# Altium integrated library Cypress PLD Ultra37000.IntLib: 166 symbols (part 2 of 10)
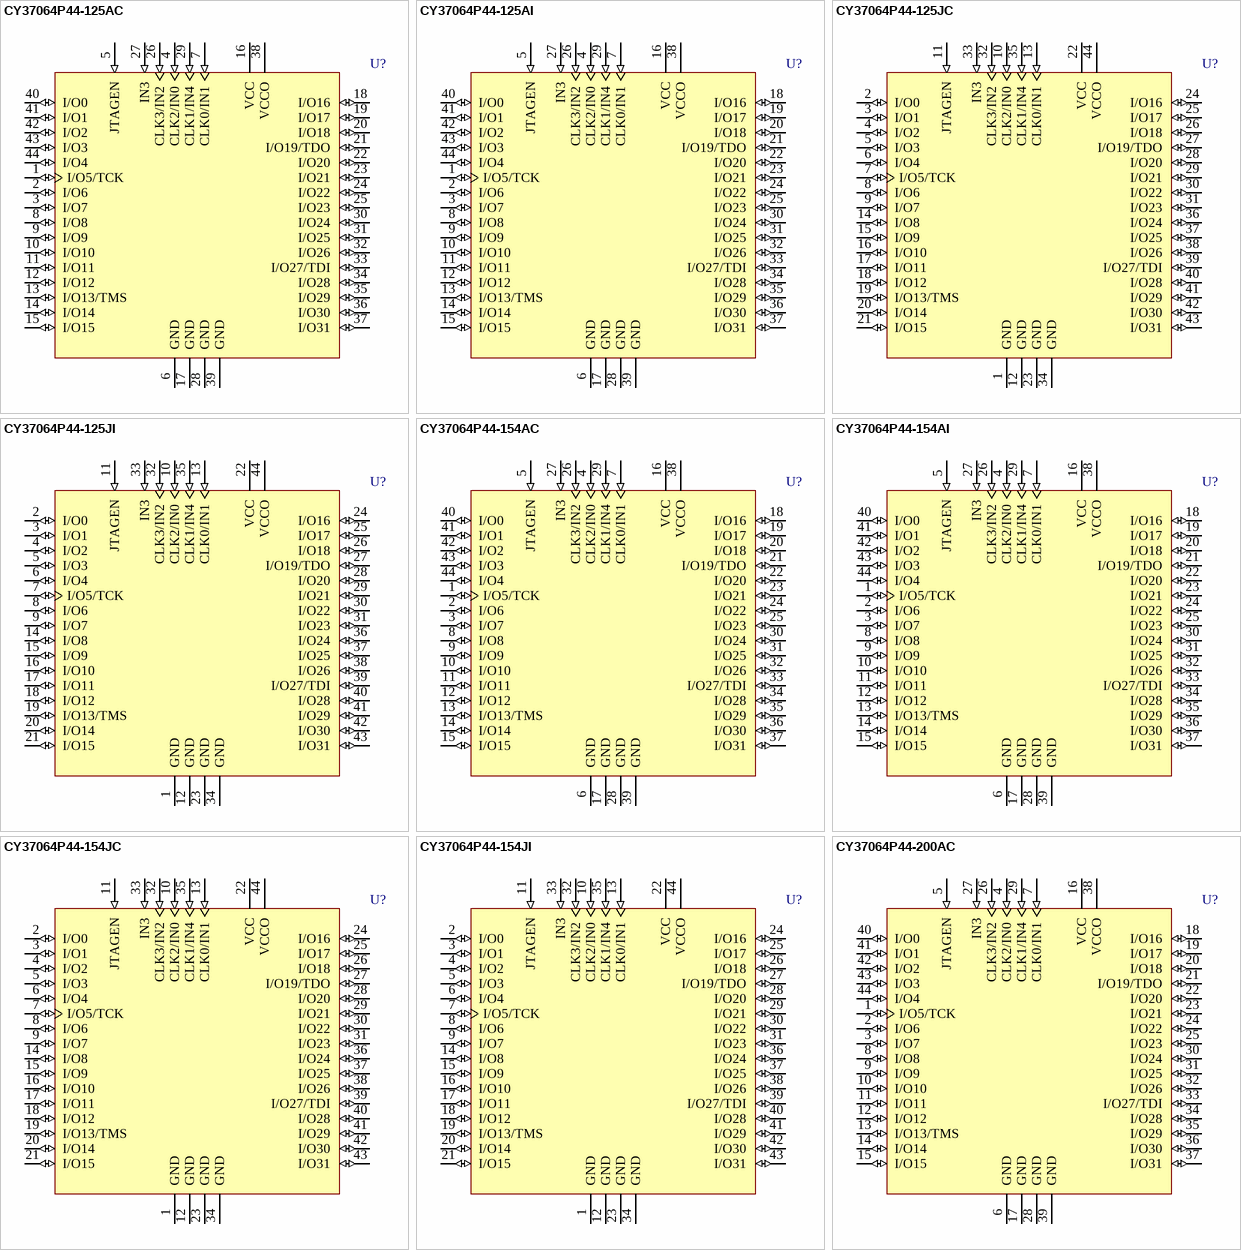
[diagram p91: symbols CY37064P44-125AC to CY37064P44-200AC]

## CY37064P44-125JC
designator U?
Ultra37000 5V, ISR High-Performance CPLD
footprint J67_N (Leaded Chip Carrier, 44-Leads, Body 16.6x16.6mm, Pitch 1.27mm, IPC Medium Density)
footprint J67_L (Leaded Chip Carrier, 44-Leads, Body 16.6x16.6mm, Pitch 1.27mm, IPC High Density)
footprint J67_M (Leaded Chip Carrier, 44-Leads, Body 16.6x16.6mm, Pitch 1.27mm, IPC Low Density)
3D model CY37064P44-J67 (44-Pin Plastic Leaded Chip Carrier 1.27 mm Pitch)
pins: 1 GND (power), 2 I/O0 (io), 3 I/O1 (io), 4 I/O2 (io), 5 I/O3 (io), 6 I/O4 (io), 7 I/O5/TCK (io), 8 I/O6 (io), 9 I/O7 (io), 10 CLK2/IN0 (in), 11 JTAGEN (in), 12 GND (power), 13 CLK0/IN1 (in), 14 I/O8 (io), 15 I/O9 (io), 16 I/O10 (io), 17 I/O11 (io), 18 I/O12 (io), 19 I/O13/TMS (io), 20 I/O14 (io), 21 I/O15 (io), 22 VCC (power), 23 GND (power), 24 I/O16 (io), 25 I/O17 (io), 26 I/O18 (io), 27 I/O19/TDO (io), 28 I/O20 (io), 29 I/O21 (io), 30 I/O22 (io), 31 I/O23 (io), 32 CLK3/IN2 (in), 33 IN3 (in), 34 GND (power), 35 CLK1/IN4 (in), 36 I/O24 (io), 37 I/O25 (io), 38 I/O26 (io), 39 I/O27/TDI (io), 40 I/O28 (io), 41 I/O29 (io), 42 I/O30 (io), 43 I/O31 (io), 44 VCCO (power)

## CY37064P44-125JI
designator U?
Ultra37000 5V, ISR High-Performance CPLD
footprint J67_N (Leaded Chip Carrier, 44-Leads, Body 16.6x16.6mm, Pitch 1.27mm, IPC Medium Density)
footprint J67_L (Leaded Chip Carrier, 44-Leads, Body 16.6x16.6mm, Pitch 1.27mm, IPC High Density)
footprint J67_M (Leaded Chip Carrier, 44-Leads, Body 16.6x16.6mm, Pitch 1.27mm, IPC Low Density)
3D model CY37064P44-J67 (44-Pin Plastic Leaded Chip Carrier 1.27 mm Pitch)
pins: 1 GND (power), 2 I/O0 (io), 3 I/O1 (io), 4 I/O2 (io), 5 I/O3 (io), 6 I/O4 (io), 7 I/O5/TCK (io), 8 I/O6 (io), 9 I/O7 (io), 10 CLK2/IN0 (in), 11 JTAGEN (in), 12 GND (power), 13 CLK0/IN1 (in), 14 I/O8 (io), 15 I/O9 (io), 16 I/O10 (io), 17 I/O11 (io), 18 I/O12 (io), 19 I/O13/TMS (io), 20 I/O14 (io), 21 I/O15 (io), 22 VCC (power), 23 GND (power), 24 I/O16 (io), 25 I/O17 (io), 26 I/O18 (io), 27 I/O19/TDO (io), 28 I/O20 (io), 29 I/O21 (io), 30 I/O22 (io), 31 I/O23 (io), 32 CLK3/IN2 (in), 33 IN3 (in), 34 GND (power), 35 CLK1/IN4 (in), 36 I/O24 (io), 37 I/O25 (io), 38 I/O26 (io), 39 I/O27/TDI (io), 40 I/O28 (io), 41 I/O29 (io), 42 I/O30 (io), 43 I/O31 (io), 44 VCCO (power)

## CY37064P44-154AC
designator U?
Ultra37000 5V, ISR High-Performance CPLD
footprint A44_N (Thin QFP, 44-Leads, Body 10x10mm, Pitch 0.8mm, IPC Medium Density)
footprint A44_L (Thin QFP, 44-Leads, Body 10x10mm, Pitch 0.8mm, IPC High Density)
footprint A44_M (Thin QFP, 44-Leads, Body 10x10mm, Pitch 0.8mm, IPC Low Density)
3D model CY37064P44-A44 (44-Pin Thin Plastic Quad Flat Pack 0.8 mm Pitch)
pins: 1 I/O5/TCK (io), 2 I/O6 (io), 3 I/O7 (io), 4 CLK2/IN0 (in), 5 JTAGEN (in), 6 GND (power), 7 CLK0/IN1 (in), 8 I/O8 (io), 9 I/O9 (io), 10 I/O10 (io), 11 I/O11 (io), 12 I/O12 (io), 13 I/O13/TMS (io), 14 I/O14 (io), 15 I/O15 (io), 16 VCC (power), 17 GND (power), 18 I/O16 (io), 19 I/O17 (io), 20 I/O18 (io), 21 I/O19/TDO (io), 22 I/O20 (io), 23 I/O21 (io), 24 I/O22 (io), 25 I/O23 (io), 26 CLK3/IN2 (in), 27 IN3 (in), 28 GND (power), 29 CLK1/IN4 (in), 30 I/O24 (io), 31 I/O25 (io), 32 I/O26 (io), 33 I/O27/TDI (io), 34 I/O28 (io), 35 I/O29 (io), 36 I/O30 (io), 37 I/O31 (io), 38 VCCO (power), 39 GND (power), 40 I/O0 (io), 41 I/O1 (io), 42 I/O2 (io), 43 I/O3 (io), 44 I/O4 (io)

## CY37064P44-154AI
designator U?
Ultra37000 5V, ISR High-Performance CPLD
footprint A44_N (Thin QFP, 44-Leads, Body 10x10mm, Pitch 0.8mm, IPC Medium Density)
footprint A44_L (Thin QFP, 44-Leads, Body 10x10mm, Pitch 0.8mm, IPC High Density)
footprint A44_M (Thin QFP, 44-Leads, Body 10x10mm, Pitch 0.8mm, IPC Low Density)
3D model CY37064P44-A44 (44-Pin Thin Plastic Quad Flat Pack 0.8 mm Pitch)
pins: 1 I/O5/TCK (io), 2 I/O6 (io), 3 I/O7 (io), 4 CLK2/IN0 (in), 5 JTAGEN (in), 6 GND (power), 7 CLK0/IN1 (in), 8 I/O8 (io), 9 I/O9 (io), 10 I/O10 (io), 11 I/O11 (io), 12 I/O12 (io), 13 I/O13/TMS (io), 14 I/O14 (io), 15 I/O15 (io), 16 VCC (power), 17 GND (power), 18 I/O16 (io), 19 I/O17 (io), 20 I/O18 (io), 21 I/O19/TDO (io), 22 I/O20 (io), 23 I/O21 (io), 24 I/O22 (io), 25 I/O23 (io), 26 CLK3/IN2 (in), 27 IN3 (in), 28 GND (power), 29 CLK1/IN4 (in), 30 I/O24 (io), 31 I/O25 (io), 32 I/O26 (io), 33 I/O27/TDI (io), 34 I/O28 (io), 35 I/O29 (io), 36 I/O30 (io), 37 I/O31 (io), 38 VCCO (power), 39 GND (power), 40 I/O0 (io), 41 I/O1 (io), 42 I/O2 (io), 43 I/O3 (io), 44 I/O4 (io)

## CY37064P44-154JC
designator U?
Ultra37000 5V, ISR High-Performance CPLD
footprint J67_N (Leaded Chip Carrier, 44-Leads, Body 16.6x16.6mm, Pitch 1.27mm, IPC Medium Density)
footprint J67_L (Leaded Chip Carrier, 44-Leads, Body 16.6x16.6mm, Pitch 1.27mm, IPC High Density)
footprint J67_M (Leaded Chip Carrier, 44-Leads, Body 16.6x16.6mm, Pitch 1.27mm, IPC Low Density)
3D model CY37064P44-J67 (44-Pin Plastic Leaded Chip Carrier 1.27 mm Pitch)
pins: 1 GND (power), 2 I/O0 (io), 3 I/O1 (io), 4 I/O2 (io), 5 I/O3 (io), 6 I/O4 (io), 7 I/O5/TCK (io), 8 I/O6 (io), 9 I/O7 (io), 10 CLK2/IN0 (in), 11 JTAGEN (in), 12 GND (power), 13 CLK0/IN1 (in), 14 I/O8 (io), 15 I/O9 (io), 16 I/O10 (io), 17 I/O11 (io), 18 I/O12 (io), 19 I/O13/TMS (io), 20 I/O14 (io), 21 I/O15 (io), 22 VCC (power), 23 GND (power), 24 I/O16 (io), 25 I/O17 (io), 26 I/O18 (io), 27 I/O19/TDO (io), 28 I/O20 (io), 29 I/O21 (io), 30 I/O22 (io), 31 I/O23 (io), 32 CLK3/IN2 (in), 33 IN3 (in), 34 GND (power), 35 CLK1/IN4 (in), 36 I/O24 (io), 37 I/O25 (io), 38 I/O26 (io), 39 I/O27/TDI (io), 40 I/O28 (io), 41 I/O29 (io), 42 I/O30 (io), 43 I/O31 (io), 44 VCCO (power)

## CY37064P44-154JI
designator U?
Ultra37000 5V, ISR High-Performance CPLD
footprint J67_N (Leaded Chip Carrier, 44-Leads, Body 16.6x16.6mm, Pitch 1.27mm, IPC Medium Density)
footprint J67_L (Leaded Chip Carrier, 44-Leads, Body 16.6x16.6mm, Pitch 1.27mm, IPC High Density)
footprint J67_M (Leaded Chip Carrier, 44-Leads, Body 16.6x16.6mm, Pitch 1.27mm, IPC Low Density)
3D model CY37064P44-J67 (44-Pin Plastic Leaded Chip Carrier 1.27 mm Pitch)
pins: 1 GND (power), 2 I/O0 (io), 3 I/O1 (io), 4 I/O2 (io), 5 I/O3 (io), 6 I/O4 (io), 7 I/O5/TCK (io), 8 I/O6 (io), 9 I/O7 (io), 10 CLK2/IN0 (in), 11 JTAGEN (in), 12 GND (power), 13 CLK0/IN1 (in), 14 I/O8 (io), 15 I/O9 (io), 16 I/O10 (io), 17 I/O11 (io), 18 I/O12 (io), 19 I/O13/TMS (io), 20 I/O14 (io), 21 I/O15 (io), 22 VCC (power), 23 GND (power), 24 I/O16 (io), 25 I/O17 (io), 26 I/O18 (io), 27 I/O19/TDO (io), 28 I/O20 (io), 29 I/O21 (io), 30 I/O22 (io), 31 I/O23 (io), 32 CLK3/IN2 (in), 33 IN3 (in), 34 GND (power), 35 CLK1/IN4 (in), 36 I/O24 (io), 37 I/O25 (io), 38 I/O26 (io), 39 I/O27/TDI (io), 40 I/O28 (io), 41 I/O29 (io), 42 I/O30 (io), 43 I/O31 (io), 44 VCCO (power)

## CY37064P44-200AC
designator U?
Ultra37000 5V, ISR High-Performance CPLD
footprint A44_N (Thin QFP, 44-Leads, Body 10x10mm, Pitch 0.8mm, IPC Medium Density)
footprint A44_L (Thin QFP, 44-Leads, Body 10x10mm, Pitch 0.8mm, IPC High Density)
footprint A44_M (Thin QFP, 44-Leads, Body 10x10mm, Pitch 0.8mm, IPC Low Density)
3D model CY37064P44-A44 (44-Pin Thin Plastic Quad Flat Pack 0.8 mm Pitch)
pins: 1 I/O5/TCK (io), 2 I/O6 (io), 3 I/O7 (io), 4 CLK2/IN0 (in), 5 JTAGEN (in), 6 GND (power), 7 CLK0/IN1 (in), 8 I/O8 (io), 9 I/O9 (io), 10 I/O10 (io), 11 I/O11 (io), 12 I/O12 (io), 13 I/O13/TMS (io), 14 I/O14 (io), 15 I/O15 (io), 16 VCC (power), 17 GND (power), 18 I/O16 (io), 19 I/O17 (io), 20 I/O18 (io), 21 I/O19/TDO (io), 22 I/O20 (io), 23 I/O21 (io), 24 I/O22 (io), 25 I/O23 (io), 26 CLK3/IN2 (in), 27 IN3 (in), 28 GND (power), 29 CLK1/IN4 (in), 30 I/O24 (io), 31 I/O25 (io), 32 I/O26 (io), 33 I/O27/TDI (io), 34 I/O28 (io), 35 I/O29 (io), 36 I/O30 (io), 37 I/O31 (io), 38 VCCO (power), 39 GND (power), 40 I/O0 (io), 41 I/O1 (io), 42 I/O2 (io), 43 I/O3 (io), 44 I/O4 (io)

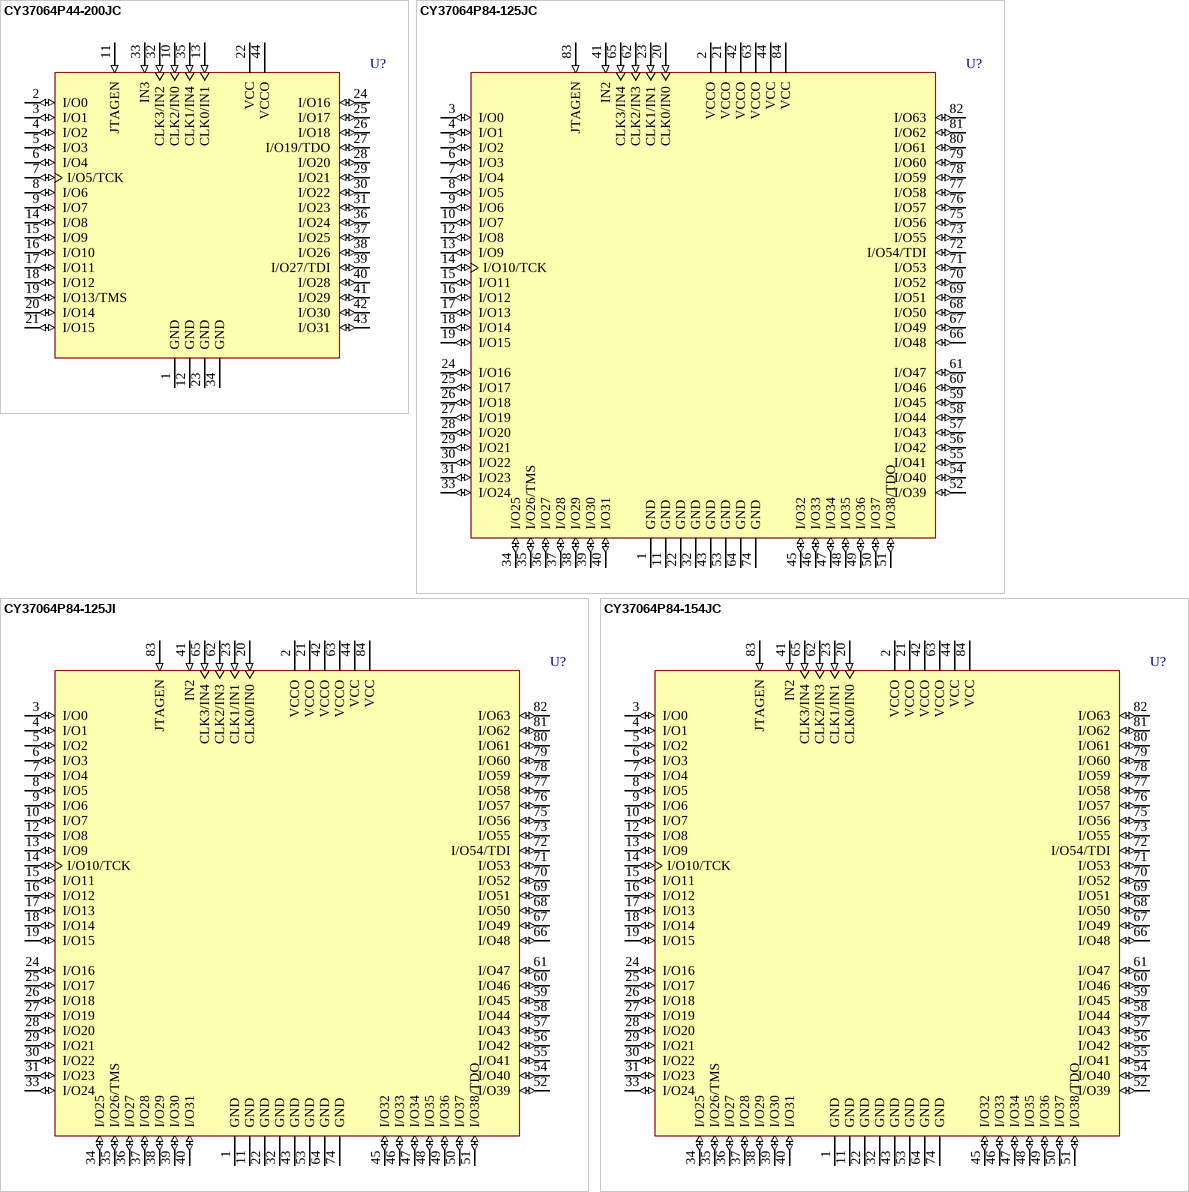
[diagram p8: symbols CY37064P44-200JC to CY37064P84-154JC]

## CY37064P44-200JC
designator U?
Ultra37000 5V, ISR High-Performance CPLD
footprint J67_N (Leaded Chip Carrier, 44-Leads, Body 16.6x16.6mm, Pitch 1.27mm, IPC Medium Density)
footprint J67_L (Leaded Chip Carrier, 44-Leads, Body 16.6x16.6mm, Pitch 1.27mm, IPC High Density)
footprint J67_M (Leaded Chip Carrier, 44-Leads, Body 16.6x16.6mm, Pitch 1.27mm, IPC Low Density)
3D model CY37064P44-J67 (44-Pin Plastic Leaded Chip Carrier 1.27 mm Pitch)
pins: 1 GND (power), 2 I/O0 (io), 3 I/O1 (io), 4 I/O2 (io), 5 I/O3 (io), 6 I/O4 (io), 7 I/O5/TCK (io), 8 I/O6 (io), 9 I/O7 (io), 10 CLK2/IN0 (in), 11 JTAGEN (in), 12 GND (power), 13 CLK0/IN1 (in), 14 I/O8 (io), 15 I/O9 (io), 16 I/O10 (io), 17 I/O11 (io), 18 I/O12 (io), 19 I/O13/TMS (io), 20 I/O14 (io), 21 I/O15 (io), 22 VCC (power), 23 GND (power), 24 I/O16 (io), 25 I/O17 (io), 26 I/O18 (io), 27 I/O19/TDO (io), 28 I/O20 (io), 29 I/O21 (io), 30 I/O22 (io), 31 I/O23 (io), 32 CLK3/IN2 (in), 33 IN3 (in), 34 GND (power), 35 CLK1/IN4 (in), 36 I/O24 (io), 37 I/O25 (io), 38 I/O26 (io), 39 I/O27/TDI (io), 40 I/O28 (io), 41 I/O29 (io), 42 I/O30 (io), 43 I/O31 (io), 44 VCCO (power)

## CY37064P84-125JC
designator U?
Ultra37000 5V, ISR High-Performance CPLD
footprint J83_N (Leaded Chip Carrier, 84-Leads, Body 29.3x29.3mm, Pitch 1.27mm, IPC Medium Density)
footprint J83_L (Leaded Chip Carrier, 84-Leads, Body 29.3x29.3mm, Pitch 1.27mm, IPC High Density)
footprint J83_M (Leaded Chip Carrier, 84-Leads, Body 29.3x29.3mm, Pitch 1.27mm, IPC Low Density)
3D model CY37064P84-J83 (84-Pin Plastic Leaded Chip Carrier 1.27 mm Pitch)
pins: 1 GND (power), 2 VCCO (power), 3 I/O0 (io), 4 I/O1 (io), 5 I/O2 (io), 6 I/O3 (io), 7 I/O4 (io), 8 I/O5 (io), 9 I/O6 (io), 10 I/O7 (io), 11 GND (power), 12 I/O8 (io), 13 I/O9 (io), 14 I/O10/TCK (io), 15 I/O11 (io), 16 I/O12 (io), 17 I/O13 (io), 18 I/O14 (io), 19 I/O15 (io), 20 CLK0/IN0 (in), 21 VCCO (power), 22 GND (power), 23 CLK1/IN1 (in), 24 I/O16 (io), 25 I/O17 (io), 26 I/O18 (io), 27 I/O19 (io), 28 I/O20 (io), 29 I/O21 (io), 30 I/O22 (io), 31 I/O23 (io), 32 GND (power), 33 I/O24 (io), 34 I/O25 (io), 35 I/O26/TMS (io), 36 I/O27 (io), 37 I/O28 (io), 38 I/O29 (io), 39 I/O30 (io), 40 I/O31 (io), 41 IN2 (in), 42 VCCO (power), 43 GND (power), 44 VCC (power), 45 I/O32 (io), 46 I/O33 (io), 47 I/O34 (io), 48 I/O35 (io), 49 I/O36 (io), 50 I/O37 (io), 51 I/O38/TDO (io), 52 I/O39 (io), 53 GND (power), 54 I/O40 (io), 55 I/O41 (io), 56 I/O42 (io), 57 I/O43 (io), 58 I/O44 (io), 59 I/O45 (io), 60 I/O46 (io), 61 I/O47 (io), 62 CLK2/IN3 (in), 63 VCCO (power), 64 GND (power), 65 CLK3/IN4 (in), 66 I/O48 (io), 67 I/O49 (io), 68 I/O50 (io), 69 I/O51 (io), 70 I/O52 (io), 71 I/O53 (io), 72 I/O54/TDI (io), 73 I/O55 (io), 74 GND (power), 75 I/O56 (io), 76 I/O57 (io), 77 I/O58 (io), 78 I/O59 (io), 79 I/O60 (io), 80 I/O61 (io), 81 I/O62 (io), 82 I/O63 (io), 83 JTAGEN (in), 84 VCC (power)

## CY37064P84-125JI
designator U?
Ultra37000 5V, ISR High-Performance CPLD
footprint J83_N (Leaded Chip Carrier, 84-Leads, Body 29.3x29.3mm, Pitch 1.27mm, IPC Medium Density)
footprint J83_L (Leaded Chip Carrier, 84-Leads, Body 29.3x29.3mm, Pitch 1.27mm, IPC High Density)
footprint J83_M (Leaded Chip Carrier, 84-Leads, Body 29.3x29.3mm, Pitch 1.27mm, IPC Low Density)
3D model CY37064P84-J83 (84-Pin Plastic Leaded Chip Carrier 1.27 mm Pitch)
pins: 1 GND (power), 2 VCCO (power), 3 I/O0 (io), 4 I/O1 (io), 5 I/O2 (io), 6 I/O3 (io), 7 I/O4 (io), 8 I/O5 (io), 9 I/O6 (io), 10 I/O7 (io), 11 GND (power), 12 I/O8 (io), 13 I/O9 (io), 14 I/O10/TCK (io), 15 I/O11 (io), 16 I/O12 (io), 17 I/O13 (io), 18 I/O14 (io), 19 I/O15 (io), 20 CLK0/IN0 (in), 21 VCCO (power), 22 GND (power), 23 CLK1/IN1 (in), 24 I/O16 (io), 25 I/O17 (io), 26 I/O18 (io), 27 I/O19 (io), 28 I/O20 (io), 29 I/O21 (io), 30 I/O22 (io), 31 I/O23 (io), 32 GND (power), 33 I/O24 (io), 34 I/O25 (io), 35 I/O26/TMS (io), 36 I/O27 (io), 37 I/O28 (io), 38 I/O29 (io), 39 I/O30 (io), 40 I/O31 (io), 41 IN2 (in), 42 VCCO (power), 43 GND (power), 44 VCC (power), 45 I/O32 (io), 46 I/O33 (io), 47 I/O34 (io), 48 I/O35 (io), 49 I/O36 (io), 50 I/O37 (io), 51 I/O38/TDO (io), 52 I/O39 (io), 53 GND (power), 54 I/O40 (io), 55 I/O41 (io), 56 I/O42 (io), 57 I/O43 (io), 58 I/O44 (io), 59 I/O45 (io), 60 I/O46 (io), 61 I/O47 (io), 62 CLK2/IN3 (in), 63 VCCO (power), 64 GND (power), 65 CLK3/IN4 (in), 66 I/O48 (io), 67 I/O49 (io), 68 I/O50 (io), 69 I/O51 (io), 70 I/O52 (io), 71 I/O53 (io), 72 I/O54/TDI (io), 73 I/O55 (io), 74 GND (power), 75 I/O56 (io), 76 I/O57 (io), 77 I/O58 (io), 78 I/O59 (io), 79 I/O60 (io), 80 I/O61 (io), 81 I/O62 (io), 82 I/O63 (io), 83 JTAGEN (in), 84 VCC (power)

## CY37064P84-154JC
designator U?
Ultra37000 5V, ISR High-Performance CPLD
footprint J83_N (Leaded Chip Carrier, 84-Leads, Body 29.3x29.3mm, Pitch 1.27mm, IPC Medium Density)
footprint J83_L (Leaded Chip Carrier, 84-Leads, Body 29.3x29.3mm, Pitch 1.27mm, IPC High Density)
footprint J83_M (Leaded Chip Carrier, 84-Leads, Body 29.3x29.3mm, Pitch 1.27mm, IPC Low Density)
3D model CY37064P84-J83 (84-Pin Plastic Leaded Chip Carrier 1.27 mm Pitch)
pins: 1 GND (power), 2 VCCO (power), 3 I/O0 (io), 4 I/O1 (io), 5 I/O2 (io), 6 I/O3 (io), 7 I/O4 (io), 8 I/O5 (io), 9 I/O6 (io), 10 I/O7 (io), 11 GND (power), 12 I/O8 (io), 13 I/O9 (io), 14 I/O10/TCK (io), 15 I/O11 (io), 16 I/O12 (io), 17 I/O13 (io), 18 I/O14 (io), 19 I/O15 (io), 20 CLK0/IN0 (in), 21 VCCO (power), 22 GND (power), 23 CLK1/IN1 (in), 24 I/O16 (io), 25 I/O17 (io), 26 I/O18 (io), 27 I/O19 (io), 28 I/O20 (io), 29 I/O21 (io), 30 I/O22 (io), 31 I/O23 (io), 32 GND (power), 33 I/O24 (io), 34 I/O25 (io), 35 I/O26/TMS (io), 36 I/O27 (io), 37 I/O28 (io), 38 I/O29 (io), 39 I/O30 (io), 40 I/O31 (io), 41 IN2 (in), 42 VCCO (power), 43 GND (power), 44 VCC (power), 45 I/O32 (io), 46 I/O33 (io), 47 I/O34 (io), 48 I/O35 (io), 49 I/O36 (io), 50 I/O37 (io), 51 I/O38/TDO (io), 52 I/O39 (io), 53 GND (power), 54 I/O40 (io), 55 I/O41 (io), 56 I/O42 (io), 57 I/O43 (io), 58 I/O44 (io), 59 I/O45 (io), 60 I/O46 (io), 61 I/O47 (io), 62 CLK2/IN3 (in), 63 VCCO (power), 64 GND (power), 65 CLK3/IN4 (in), 66 I/O48 (io), 67 I/O49 (io), 68 I/O50 (io), 69 I/O51 (io), 70 I/O52 (io), 71 I/O53 (io), 72 I/O54/TDI (io), 73 I/O55 (io), 74 GND (power), 75 I/O56 (io), 76 I/O57 (io), 77 I/O58 (io), 78 I/O59 (io), 79 I/O60 (io), 80 I/O61 (io), 81 I/O62 (io), 82 I/O63 (io), 83 JTAGEN (in), 84 VCC (power)

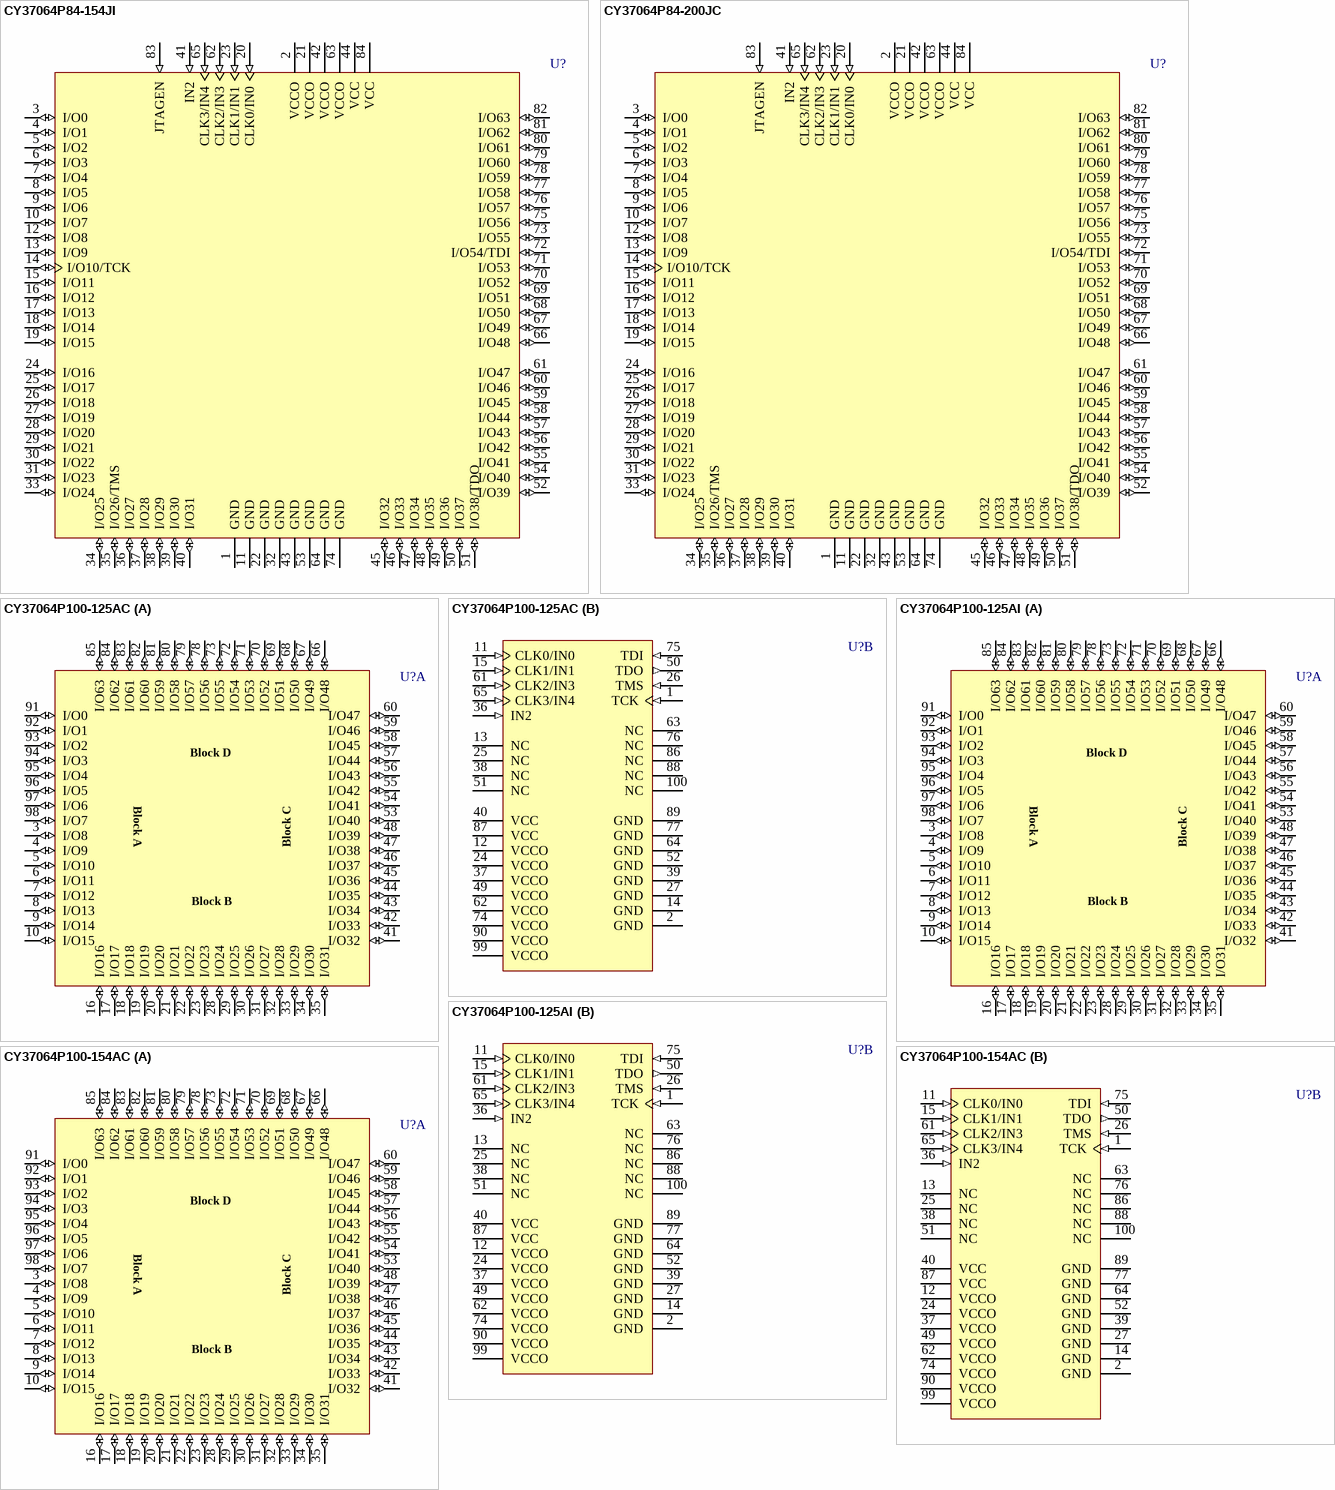
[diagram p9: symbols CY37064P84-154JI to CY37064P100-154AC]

## CY37064P84-154JI
designator U?
Ultra37000 5V, ISR High-Performance CPLD
footprint J83_N (Leaded Chip Carrier, 84-Leads, Body 29.3x29.3mm, Pitch 1.27mm, IPC Medium Density)
footprint J83_L (Leaded Chip Carrier, 84-Leads, Body 29.3x29.3mm, Pitch 1.27mm, IPC High Density)
footprint J83_M (Leaded Chip Carrier, 84-Leads, Body 29.3x29.3mm, Pitch 1.27mm, IPC Low Density)
3D model CY37064P84-J83 (84-Pin Plastic Leaded Chip Carrier 1.27 mm Pitch)
pins: 1 GND (power), 2 VCCO (power), 3 I/O0 (io), 4 I/O1 (io), 5 I/O2 (io), 6 I/O3 (io), 7 I/O4 (io), 8 I/O5 (io), 9 I/O6 (io), 10 I/O7 (io), 11 GND (power), 12 I/O8 (io), 13 I/O9 (io), 14 I/O10/TCK (io), 15 I/O11 (io), 16 I/O12 (io), 17 I/O13 (io), 18 I/O14 (io), 19 I/O15 (io), 20 CLK0/IN0 (in), 21 VCCO (power), 22 GND (power), 23 CLK1/IN1 (in), 24 I/O16 (io), 25 I/O17 (io), 26 I/O18 (io), 27 I/O19 (io), 28 I/O20 (io), 29 I/O21 (io), 30 I/O22 (io), 31 I/O23 (io), 32 GND (power), 33 I/O24 (io), 34 I/O25 (io), 35 I/O26/TMS (io), 36 I/O27 (io), 37 I/O28 (io), 38 I/O29 (io), 39 I/O30 (io), 40 I/O31 (io), 41 IN2 (in), 42 VCCO (power), 43 GND (power), 44 VCC (power), 45 I/O32 (io), 46 I/O33 (io), 47 I/O34 (io), 48 I/O35 (io), 49 I/O36 (io), 50 I/O37 (io), 51 I/O38/TDO (io), 52 I/O39 (io), 53 GND (power), 54 I/O40 (io), 55 I/O41 (io), 56 I/O42 (io), 57 I/O43 (io), 58 I/O44 (io), 59 I/O45 (io), 60 I/O46 (io), 61 I/O47 (io), 62 CLK2/IN3 (in), 63 VCCO (power), 64 GND (power), 65 CLK3/IN4 (in), 66 I/O48 (io), 67 I/O49 (io), 68 I/O50 (io), 69 I/O51 (io), 70 I/O52 (io), 71 I/O53 (io), 72 I/O54/TDI (io), 73 I/O55 (io), 74 GND (power), 75 I/O56 (io), 76 I/O57 (io), 77 I/O58 (io), 78 I/O59 (io), 79 I/O60 (io), 80 I/O61 (io), 81 I/O62 (io), 82 I/O63 (io), 83 JTAGEN (in), 84 VCC (power)

## CY37064P84-200JC
designator U?
Ultra37000 5V, ISR High-Performance CPLD
footprint J83_N (Leaded Chip Carrier, 84-Leads, Body 29.3x29.3mm, Pitch 1.27mm, IPC Medium Density)
footprint J83_L (Leaded Chip Carrier, 84-Leads, Body 29.3x29.3mm, Pitch 1.27mm, IPC High Density)
footprint J83_M (Leaded Chip Carrier, 84-Leads, Body 29.3x29.3mm, Pitch 1.27mm, IPC Low Density)
3D model CY37064P84-J83 (84-Pin Plastic Leaded Chip Carrier 1.27 mm Pitch)
pins: 1 GND (power), 2 VCCO (power), 3 I/O0 (io), 4 I/O1 (io), 5 I/O2 (io), 6 I/O3 (io), 7 I/O4 (io), 8 I/O5 (io), 9 I/O6 (io), 10 I/O7 (io), 11 GND (power), 12 I/O8 (io), 13 I/O9 (io), 14 I/O10/TCK (io), 15 I/O11 (io), 16 I/O12 (io), 17 I/O13 (io), 18 I/O14 (io), 19 I/O15 (io), 20 CLK0/IN0 (in), 21 VCCO (power), 22 GND (power), 23 CLK1/IN1 (in), 24 I/O16 (io), 25 I/O17 (io), 26 I/O18 (io), 27 I/O19 (io), 28 I/O20 (io), 29 I/O21 (io), 30 I/O22 (io), 31 I/O23 (io), 32 GND (power), 33 I/O24 (io), 34 I/O25 (io), 35 I/O26/TMS (io), 36 I/O27 (io), 37 I/O28 (io), 38 I/O29 (io), 39 I/O30 (io), 40 I/O31 (io), 41 IN2 (in), 42 VCCO (power), 43 GND (power), 44 VCC (power), 45 I/O32 (io), 46 I/O33 (io), 47 I/O34 (io), 48 I/O35 (io), 49 I/O36 (io), 50 I/O37 (io), 51 I/O38/TDO (io), 52 I/O39 (io), 53 GND (power), 54 I/O40 (io), 55 I/O41 (io), 56 I/O42 (io), 57 I/O43 (io), 58 I/O44 (io), 59 I/O45 (io), 60 I/O46 (io), 61 I/O47 (io), 62 CLK2/IN3 (in), 63 VCCO (power), 64 GND (power), 65 CLK3/IN4 (in), 66 I/O48 (io), 67 I/O49 (io), 68 I/O50 (io), 69 I/O51 (io), 70 I/O52 (io), 71 I/O53 (io), 72 I/O54/TDI (io), 73 I/O55 (io), 74 GND (power), 75 I/O56 (io), 76 I/O57 (io), 77 I/O58 (io), 78 I/O59 (io), 79 I/O60 (io), 80 I/O61 (io), 81 I/O62 (io), 82 I/O63 (io), 83 JTAGEN (in), 84 VCC (power)

## CY37064P100-125AC
designator U?
Ultra37000 5V, ISR High-Performance CPLD
footprint A100_N (Thin QFP, 100-Leads, Body 14x14mm, Pitch 0.5mm, IPC Medium Density)
footprint A100_L (Thin QFP, 100-Leads, Body 14x14mm, Pitch 0.5mm, IPC High Density)
footprint A100_M (Thin QFP, 100-Leads, Body 14x14mm, Pitch 0.5mm, IPC Low Density)
3D model CY37064P100-A100 (100-Pin Thin Quad Flat Pack 0.5 mm Pitch)
part A pins: 3 I/O8 (io), 4 I/O9 (io), 5 I/O10 (io), 6 I/O11 (io), 7 I/O12 (io), 8 I/O13 (io), 9 I/O14 (io), 10 I/O15 (io), 16 I/O16 (io), 17 I/O17 (io), 18 I/O18 (io), 19 I/O19 (io), 20 I/O20 (io), 21 I/O21 (io), 22 I/O22 (io), 23 I/O23 (io), 28 I/O24 (io), 29 I/O25 (io), 30 I/O26 (io), 31 I/O27 (io), 32 I/O28 (io), 33 I/O29 (io), 34 I/O30 (io), 35 I/O31 (io), 41 I/O32 (io), 42 I/O33 (io), 43 I/O34 (io), 44 I/O35 (io), 45 I/O36 (io), 46 I/O37 (io), 47 I/O38 (io), 48 I/O39 (io), 53 I/O40 (io), 54 I/O41 (io), 55 I/O42 (io), 56 I/O43 (io), 57 I/O44 (io), 58 I/O45 (io), 59 I/O46 (io), 60 I/O47 (io), 66 I/O48 (io), 67 I/O49 (io), 68 I/O50 (io), 69 I/O51 (io), 70 I/O52 (io), 71 I/O53 (io), 72 I/O54 (io), 73 I/O55 (io), 78 I/O56 (io), 79 I/O57 (io), 80 I/O58 (io), 81 I/O59 (io), 82 I/O60 (io), 83 I/O61 (io), 84 I/O62 (io), 85 I/O63 (io), 91 I/O0 (io), 92 I/O1 (io), 93 I/O2 (io), 94 I/O3 (io), 95 I/O4 (io), 96 I/O5 (io), 97 I/O6 (io), 98 I/O7 (io)
part B pins: 1 TCK (in), 2 GND (power), 11 CLK0/IN0 (in), 12 VCCO (power), 13 NC, 14 GND (power), 15 CLK1/IN1 (in), 24 VCCO (power), 25 NC, 26 TMS (in), 27 GND (power), 36 IN2 (in), 37 VCCO (power), 38 NC, 39 GND (power), 40 VCC (power), 49 VCCO (power), 50 TDO (out), 51 NC, 52 GND (power), 61 CLK2/IN3 (in), 62 VCCO (power), 63 NC, 64 GND (power), 65 CLK3/IN4 (in), 74 VCCO (power), 75 TDI (in), 76 NC, 77 GND (power), 86 NC, 87 VCC (power), 88 NC, 89 GND (power), 90 VCCO (power), 99 VCCO (power), 100 NC

## CY37064P100-125AI
designator U?
Ultra37000 5V, ISR High-Performance CPLD
footprint A100_N (Thin QFP, 100-Leads, Body 14x14mm, Pitch 0.5mm, IPC Medium Density)
footprint A100_L (Thin QFP, 100-Leads, Body 14x14mm, Pitch 0.5mm, IPC High Density)
footprint A100_M (Thin QFP, 100-Leads, Body 14x14mm, Pitch 0.5mm, IPC Low Density)
3D model CY37064P100-A100 (100-Pin Thin Quad Flat Pack 0.5 mm Pitch)
part A pins: 3 I/O8 (io), 4 I/O9 (io), 5 I/O10 (io), 6 I/O11 (io), 7 I/O12 (io), 8 I/O13 (io), 9 I/O14 (io), 10 I/O15 (io), 16 I/O16 (io), 17 I/O17 (io), 18 I/O18 (io), 19 I/O19 (io), 20 I/O20 (io), 21 I/O21 (io), 22 I/O22 (io), 23 I/O23 (io), 28 I/O24 (io), 29 I/O25 (io), 30 I/O26 (io), 31 I/O27 (io), 32 I/O28 (io), 33 I/O29 (io), 34 I/O30 (io), 35 I/O31 (io), 41 I/O32 (io), 42 I/O33 (io), 43 I/O34 (io), 44 I/O35 (io), 45 I/O36 (io), 46 I/O37 (io), 47 I/O38 (io), 48 I/O39 (io), 53 I/O40 (io), 54 I/O41 (io), 55 I/O42 (io), 56 I/O43 (io), 57 I/O44 (io), 58 I/O45 (io), 59 I/O46 (io), 60 I/O47 (io), 66 I/O48 (io), 67 I/O49 (io), 68 I/O50 (io), 69 I/O51 (io), 70 I/O52 (io), 71 I/O53 (io), 72 I/O54 (io), 73 I/O55 (io), 78 I/O56 (io), 79 I/O57 (io), 80 I/O58 (io), 81 I/O59 (io), 82 I/O60 (io), 83 I/O61 (io), 84 I/O62 (io), 85 I/O63 (io), 91 I/O0 (io), 92 I/O1 (io), 93 I/O2 (io), 94 I/O3 (io), 95 I/O4 (io), 96 I/O5 (io), 97 I/O6 (io), 98 I/O7 (io)
part B pins: 1 TCK (in), 2 GND (power), 11 CLK0/IN0 (in), 12 VCCO (power), 13 NC, 14 GND (power), 15 CLK1/IN1 (in), 24 VCCO (power), 25 NC, 26 TMS (in), 27 GND (power), 36 IN2 (in), 37 VCCO (power), 38 NC, 39 GND (power), 40 VCC (power), 49 VCCO (power), 50 TDO (out), 51 NC, 52 GND (power), 61 CLK2/IN3 (in), 62 VCCO (power), 63 NC, 64 GND (power), 65 CLK3/IN4 (in), 74 VCCO (power), 75 TDI (in), 76 NC, 77 GND (power), 86 NC, 87 VCC (power), 88 NC, 89 GND (power), 90 VCCO (power), 99 VCCO (power), 100 NC

## CY37064P100-154AC
designator U?
Ultra37000 5V, ISR High-Performance CPLD
footprint A100_N (Thin QFP, 100-Leads, Body 14x14mm, Pitch 0.5mm, IPC Medium Density)
footprint A100_L (Thin QFP, 100-Leads, Body 14x14mm, Pitch 0.5mm, IPC High Density)
footprint A100_M (Thin QFP, 100-Leads, Body 14x14mm, Pitch 0.5mm, IPC Low Density)
3D model CY37064P100-A100 (100-Pin Thin Quad Flat Pack 0.5 mm Pitch)
part A pins: 3 I/O8 (io), 4 I/O9 (io), 5 I/O10 (io), 6 I/O11 (io), 7 I/O12 (io), 8 I/O13 (io), 9 I/O14 (io), 10 I/O15 (io), 16 I/O16 (io), 17 I/O17 (io), 18 I/O18 (io), 19 I/O19 (io), 20 I/O20 (io), 21 I/O21 (io), 22 I/O22 (io), 23 I/O23 (io), 28 I/O24 (io), 29 I/O25 (io), 30 I/O26 (io), 31 I/O27 (io), 32 I/O28 (io), 33 I/O29 (io), 34 I/O30 (io), 35 I/O31 (io), 41 I/O32 (io), 42 I/O33 (io), 43 I/O34 (io), 44 I/O35 (io), 45 I/O36 (io), 46 I/O37 (io), 47 I/O38 (io), 48 I/O39 (io), 53 I/O40 (io), 54 I/O41 (io), 55 I/O42 (io), 56 I/O43 (io), 57 I/O44 (io), 58 I/O45 (io), 59 I/O46 (io), 60 I/O47 (io), 66 I/O48 (io), 67 I/O49 (io), 68 I/O50 (io), 69 I/O51 (io), 70 I/O52 (io), 71 I/O53 (io), 72 I/O54 (io), 73 I/O55 (io), 78 I/O56 (io), 79 I/O57 (io), 80 I/O58 (io), 81 I/O59 (io), 82 I/O60 (io), 83 I/O61 (io), 84 I/O62 (io), 85 I/O63 (io), 91 I/O0 (io), 92 I/O1 (io), 93 I/O2 (io), 94 I/O3 (io), 95 I/O4 (io), 96 I/O5 (io), 97 I/O6 (io), 98 I/O7 (io)
part B pins: 1 TCK (in), 2 GND (power), 11 CLK0/IN0 (in), 12 VCCO (power), 13 NC, 14 GND (power), 15 CLK1/IN1 (in), 24 VCCO (power), 25 NC, 26 TMS (in), 27 GND (power), 36 IN2 (in), 37 VCCO (power), 38 NC, 39 GND (power), 40 VCC (power), 49 VCCO (power), 50 TDO (out), 51 NC, 52 GND (power), 61 CLK2/IN3 (in), 62 VCCO (power), 63 NC, 64 GND (power), 65 CLK3/IN4 (in), 74 VCCO (power), 75 TDI (in), 76 NC, 77 GND (power), 86 NC, 87 VCC (power), 88 NC, 89 GND (power), 90 VCCO (power), 99 VCCO (power), 100 NC

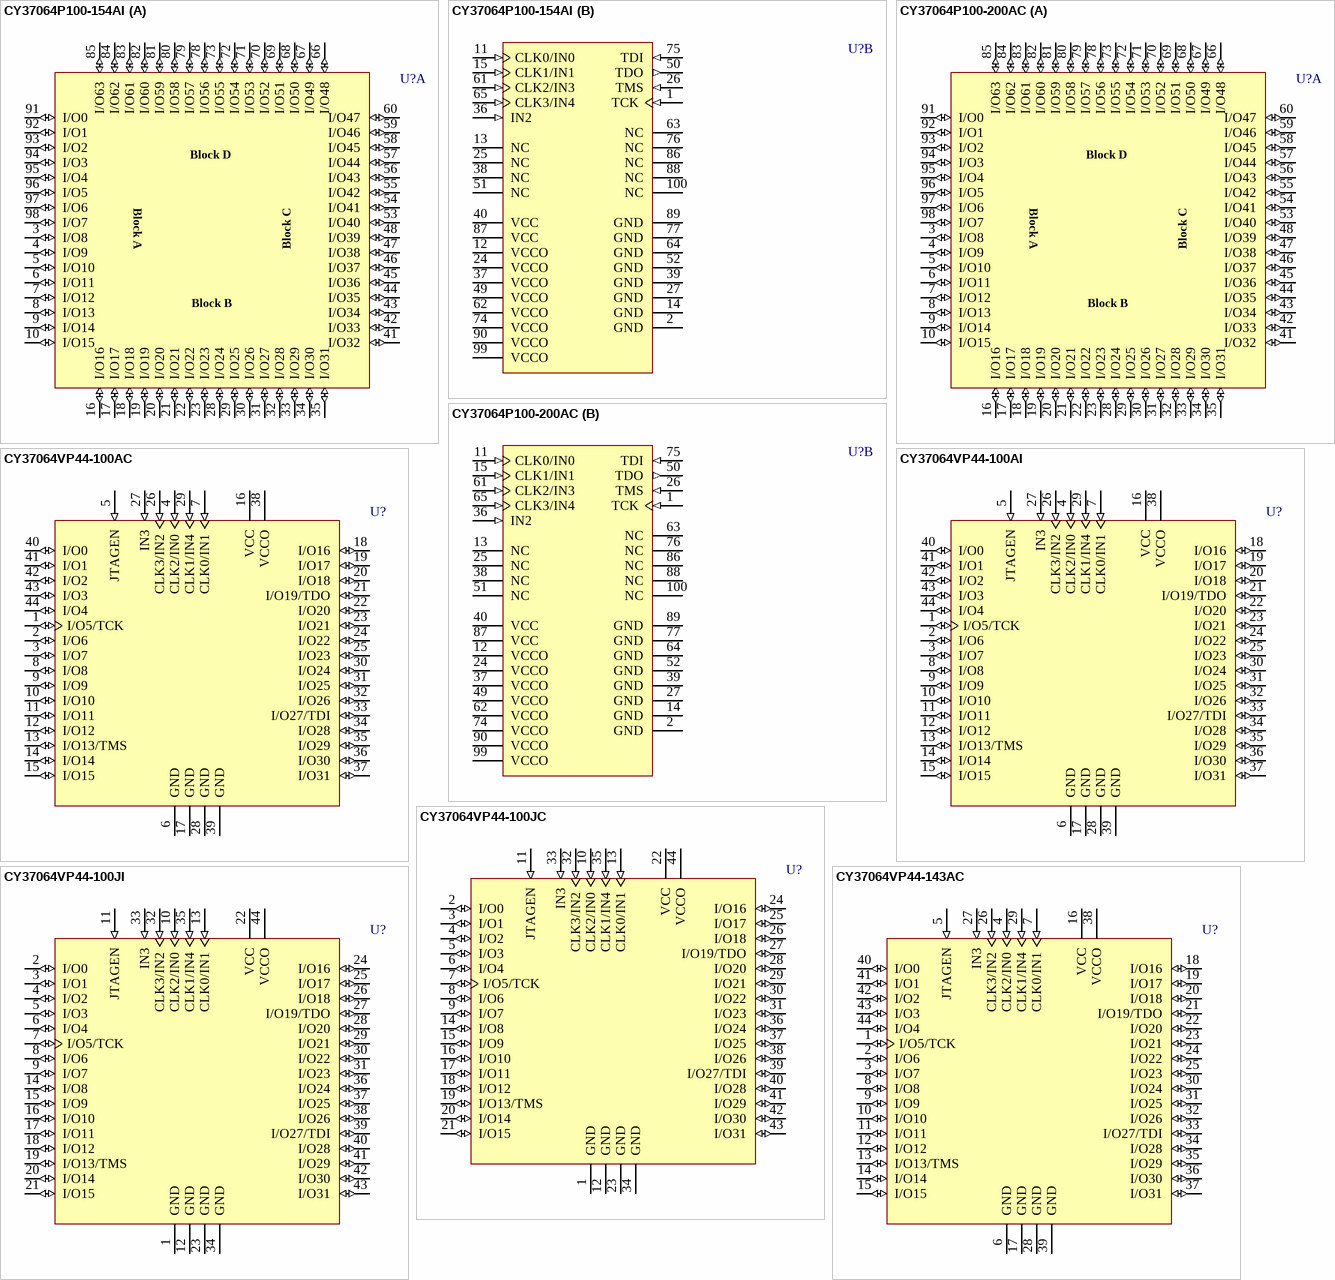
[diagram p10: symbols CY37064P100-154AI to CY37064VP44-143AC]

## CY37064P100-154AI
designator U?
Ultra37000 5V, ISR High-Performance CPLD
footprint A100_N (Thin QFP, 100-Leads, Body 14x14mm, Pitch 0.5mm, IPC Medium Density)
footprint A100_L (Thin QFP, 100-Leads, Body 14x14mm, Pitch 0.5mm, IPC High Density)
footprint A100_M (Thin QFP, 100-Leads, Body 14x14mm, Pitch 0.5mm, IPC Low Density)
3D model CY37064P100-A100 (100-Pin Thin Quad Flat Pack 0.5 mm Pitch)
part A pins: 3 I/O8 (io), 4 I/O9 (io), 5 I/O10 (io), 6 I/O11 (io), 7 I/O12 (io), 8 I/O13 (io), 9 I/O14 (io), 10 I/O15 (io), 16 I/O16 (io), 17 I/O17 (io), 18 I/O18 (io), 19 I/O19 (io), 20 I/O20 (io), 21 I/O21 (io), 22 I/O22 (io), 23 I/O23 (io), 28 I/O24 (io), 29 I/O25 (io), 30 I/O26 (io), 31 I/O27 (io), 32 I/O28 (io), 33 I/O29 (io), 34 I/O30 (io), 35 I/O31 (io), 41 I/O32 (io), 42 I/O33 (io), 43 I/O34 (io), 44 I/O35 (io), 45 I/O36 (io), 46 I/O37 (io), 47 I/O38 (io), 48 I/O39 (io), 53 I/O40 (io), 54 I/O41 (io), 55 I/O42 (io), 56 I/O43 (io), 57 I/O44 (io), 58 I/O45 (io), 59 I/O46 (io), 60 I/O47 (io), 66 I/O48 (io), 67 I/O49 (io), 68 I/O50 (io), 69 I/O51 (io), 70 I/O52 (io), 71 I/O53 (io), 72 I/O54 (io), 73 I/O55 (io), 78 I/O56 (io), 79 I/O57 (io), 80 I/O58 (io), 81 I/O59 (io), 82 I/O60 (io), 83 I/O61 (io), 84 I/O62 (io), 85 I/O63 (io), 91 I/O0 (io), 92 I/O1 (io), 93 I/O2 (io), 94 I/O3 (io), 95 I/O4 (io), 96 I/O5 (io), 97 I/O6 (io), 98 I/O7 (io)
part B pins: 1 TCK (in), 2 GND (power), 11 CLK0/IN0 (in), 12 VCCO (power), 13 NC, 14 GND (power), 15 CLK1/IN1 (in), 24 VCCO (power), 25 NC, 26 TMS (in), 27 GND (power), 36 IN2 (in), 37 VCCO (power), 38 NC, 39 GND (power), 40 VCC (power), 49 VCCO (power), 50 TDO (out), 51 NC, 52 GND (power), 61 CLK2/IN3 (in), 62 VCCO (power), 63 NC, 64 GND (power), 65 CLK3/IN4 (in), 74 VCCO (power), 75 TDI (in), 76 NC, 77 GND (power), 86 NC, 87 VCC (power), 88 NC, 89 GND (power), 90 VCCO (power), 99 VCCO (power), 100 NC

## CY37064P100-200AC
designator U?
Ultra37000 5V, ISR High-Performance CPLD
footprint A100_N (Thin QFP, 100-Leads, Body 14x14mm, Pitch 0.5mm, IPC Medium Density)
footprint A100_L (Thin QFP, 100-Leads, Body 14x14mm, Pitch 0.5mm, IPC High Density)
footprint A100_M (Thin QFP, 100-Leads, Body 14x14mm, Pitch 0.5mm, IPC Low Density)
3D model CY37064P100-A100 (100-Pin Thin Quad Flat Pack 0.5 mm Pitch)
part A pins: 3 I/O8 (io), 4 I/O9 (io), 5 I/O10 (io), 6 I/O11 (io), 7 I/O12 (io), 8 I/O13 (io), 9 I/O14 (io), 10 I/O15 (io), 16 I/O16 (io), 17 I/O17 (io), 18 I/O18 (io), 19 I/O19 (io), 20 I/O20 (io), 21 I/O21 (io), 22 I/O22 (io), 23 I/O23 (io), 28 I/O24 (io), 29 I/O25 (io), 30 I/O26 (io), 31 I/O27 (io), 32 I/O28 (io), 33 I/O29 (io), 34 I/O30 (io), 35 I/O31 (io), 41 I/O32 (io), 42 I/O33 (io), 43 I/O34 (io), 44 I/O35 (io), 45 I/O36 (io), 46 I/O37 (io), 47 I/O38 (io), 48 I/O39 (io), 53 I/O40 (io), 54 I/O41 (io), 55 I/O42 (io), 56 I/O43 (io), 57 I/O44 (io), 58 I/O45 (io), 59 I/O46 (io), 60 I/O47 (io), 66 I/O48 (io), 67 I/O49 (io), 68 I/O50 (io), 69 I/O51 (io), 70 I/O52 (io), 71 I/O53 (io), 72 I/O54 (io), 73 I/O55 (io), 78 I/O56 (io), 79 I/O57 (io), 80 I/O58 (io), 81 I/O59 (io), 82 I/O60 (io), 83 I/O61 (io), 84 I/O62 (io), 85 I/O63 (io), 91 I/O0 (io), 92 I/O1 (io), 93 I/O2 (io), 94 I/O3 (io), 95 I/O4 (io), 96 I/O5 (io), 97 I/O6 (io), 98 I/O7 (io)
part B pins: 1 TCK (in), 2 GND (power), 11 CLK0/IN0 (in), 12 VCCO (power), 13 NC, 14 GND (power), 15 CLK1/IN1 (in), 24 VCCO (power), 25 NC, 26 TMS (in), 27 GND (power), 36 IN2 (in), 37 VCCO (power), 38 NC, 39 GND (power), 40 VCC (power), 49 VCCO (power), 50 TDO (out), 51 NC, 52 GND (power), 61 CLK2/IN3 (in), 62 VCCO (power), 63 NC, 64 GND (power), 65 CLK3/IN4 (in), 74 VCCO (power), 75 TDI (in), 76 NC, 77 GND (power), 86 NC, 87 VCC (power), 88 NC, 89 GND (power), 90 VCCO (power), 99 VCCO (power), 100 NC

## CY37064VP44-100AC
designator U?
Ultra37000 3.3V, ISR High-Performance CPLD
footprint A44_N (Thin QFP, 44-Leads, Body 10x10mm, Pitch 0.8mm, IPC Medium Density)
footprint A44_L (Thin QFP, 44-Leads, Body 10x10mm, Pitch 0.8mm, IPC High Density)
footprint A44_M (Thin QFP, 44-Leads, Body 10x10mm, Pitch 0.8mm, IPC Low Density)
3D model CY37064VP44-A44 (44-Pin Thin Plastic Quad Flat Pack 0.8 mm Pitch)
pins: 1 I/O5/TCK (io), 2 I/O6 (io), 3 I/O7 (io), 4 CLK2/IN0 (in), 5 JTAGEN (in), 6 GND (power), 7 CLK0/IN1 (in), 8 I/O8 (io), 9 I/O9 (io), 10 I/O10 (io), 11 I/O11 (io), 12 I/O12 (io), 13 I/O13/TMS (io), 14 I/O14 (io), 15 I/O15 (io), 16 VCC (power), 17 GND (power), 18 I/O16 (io), 19 I/O17 (io), 20 I/O18 (io), 21 I/O19/TDO (io), 22 I/O20 (io), 23 I/O21 (io), 24 I/O22 (io), 25 I/O23 (io), 26 CLK3/IN2 (in), 27 IN3 (in), 28 GND (power), 29 CLK1/IN4 (in), 30 I/O24 (io), 31 I/O25 (io), 32 I/O26 (io), 33 I/O27/TDI (io), 34 I/O28 (io), 35 I/O29 (io), 36 I/O30 (io), 37 I/O31 (io), 38 VCCO (power), 39 GND (power), 40 I/O0 (io), 41 I/O1 (io), 42 I/O2 (io), 43 I/O3 (io), 44 I/O4 (io)

## CY37064VP44-100AI
designator U?
Ultra37000 3.3V, ISR High-Performance CPLD
footprint A44_N (Thin QFP, 44-Leads, Body 10x10mm, Pitch 0.8mm, IPC Medium Density)
footprint A44_L (Thin QFP, 44-Leads, Body 10x10mm, Pitch 0.8mm, IPC High Density)
footprint A44_M (Thin QFP, 44-Leads, Body 10x10mm, Pitch 0.8mm, IPC Low Density)
3D model CY37064VP44-A44 (44-Pin Thin Plastic Quad Flat Pack 0.8 mm Pitch)
pins: 1 I/O5/TCK (io), 2 I/O6 (io), 3 I/O7 (io), 4 CLK2/IN0 (in), 5 JTAGEN (in), 6 GND (power), 7 CLK0/IN1 (in), 8 I/O8 (io), 9 I/O9 (io), 10 I/O10 (io), 11 I/O11 (io), 12 I/O12 (io), 13 I/O13/TMS (io), 14 I/O14 (io), 15 I/O15 (io), 16 VCC (power), 17 GND (power), 18 I/O16 (io), 19 I/O17 (io), 20 I/O18 (io), 21 I/O19/TDO (io), 22 I/O20 (io), 23 I/O21 (io), 24 I/O22 (io), 25 I/O23 (io), 26 CLK3/IN2 (in), 27 IN3 (in), 28 GND (power), 29 CLK1/IN4 (in), 30 I/O24 (io), 31 I/O25 (io), 32 I/O26 (io), 33 I/O27/TDI (io), 34 I/O28 (io), 35 I/O29 (io), 36 I/O30 (io), 37 I/O31 (io), 38 VCCO (power), 39 GND (power), 40 I/O0 (io), 41 I/O1 (io), 42 I/O2 (io), 43 I/O3 (io), 44 I/O4 (io)

## CY37064VP44-100JC
designator U?
Ultra37000 3.3V, ISR High-Performance CPLD; ComponentAvailability: Obsolete
footprint J67_N (Leaded Chip Carrier, 44-Leads, Body 16.6x16.6mm, Pitch 1.27mm, IPC Medium Density)
footprint J67_L (Leaded Chip Carrier, 44-Leads, Body 16.6x16.6mm, Pitch 1.27mm, IPC High Density)
footprint J67_M (Leaded Chip Carrier, 44-Leads, Body 16.6x16.6mm, Pitch 1.27mm, IPC Low Density)
3D model CY37064VP44-J67 (44-Pin Plastic Leaded Chip Carrier 1.27 mm Pitch)
pins: 1 GND (power), 2 I/O0 (io), 3 I/O1 (io), 4 I/O2 (io), 5 I/O3 (io), 6 I/O4 (io), 7 I/O5/TCK (io), 8 I/O6 (io), 9 I/O7 (io), 10 CLK2/IN0 (in), 11 JTAGEN (in), 12 GND (power), 13 CLK0/IN1 (in), 14 I/O8 (io), 15 I/O9 (io), 16 I/O10 (io), 17 I/O11 (io), 18 I/O12 (io), 19 I/O13/TMS (io), 20 I/O14 (io), 21 I/O15 (io), 22 VCC (power), 23 GND (power), 24 I/O16 (io), 25 I/O17 (io), 26 I/O18 (io), 27 I/O19/TDO (io), 28 I/O20 (io), 29 I/O21 (io), 30 I/O22 (io), 31 I/O23 (io), 32 CLK3/IN2 (in), 33 IN3 (in), 34 GND (power), 35 CLK1/IN4 (in), 36 I/O24 (io), 37 I/O25 (io), 38 I/O26 (io), 39 I/O27/TDI (io), 40 I/O28 (io), 41 I/O29 (io), 42 I/O30 (io), 43 I/O31 (io), 44 VCCO (power)

## CY37064VP44-100JI
designator U?
Ultra37000 3.3V, ISR High-Performance CPLD; ComponentAvailability: Obsolete
footprint J67_N (Leaded Chip Carrier, 44-Leads, Body 16.6x16.6mm, Pitch 1.27mm, IPC Medium Density)
footprint J67_L (Leaded Chip Carrier, 44-Leads, Body 16.6x16.6mm, Pitch 1.27mm, IPC High Density)
footprint J67_M (Leaded Chip Carrier, 44-Leads, Body 16.6x16.6mm, Pitch 1.27mm, IPC Low Density)
3D model CY37064VP44-J67 (44-Pin Plastic Leaded Chip Carrier 1.27 mm Pitch)
pins: 1 GND (power), 2 I/O0 (io), 3 I/O1 (io), 4 I/O2 (io), 5 I/O3 (io), 6 I/O4 (io), 7 I/O5/TCK (io), 8 I/O6 (io), 9 I/O7 (io), 10 CLK2/IN0 (in), 11 JTAGEN (in), 12 GND (power), 13 CLK0/IN1 (in), 14 I/O8 (io), 15 I/O9 (io), 16 I/O10 (io), 17 I/O11 (io), 18 I/O12 (io), 19 I/O13/TMS (io), 20 I/O14 (io), 21 I/O15 (io), 22 VCC (power), 23 GND (power), 24 I/O16 (io), 25 I/O17 (io), 26 I/O18 (io), 27 I/O19/TDO (io), 28 I/O20 (io), 29 I/O21 (io), 30 I/O22 (io), 31 I/O23 (io), 32 CLK3/IN2 (in), 33 IN3 (in), 34 GND (power), 35 CLK1/IN4 (in), 36 I/O24 (io), 37 I/O25 (io), 38 I/O26 (io), 39 I/O27/TDI (io), 40 I/O28 (io), 41 I/O29 (io), 42 I/O30 (io), 43 I/O31 (io), 44 VCCO (power)

## CY37064VP44-143AC
designator U?
Ultra37000 3.3V, ISR High-Performance CPLD
footprint A44_N (Thin QFP, 44-Leads, Body 10x10mm, Pitch 0.8mm, IPC Medium Density)
footprint A44_L (Thin QFP, 44-Leads, Body 10x10mm, Pitch 0.8mm, IPC High Density)
footprint A44_M (Thin QFP, 44-Leads, Body 10x10mm, Pitch 0.8mm, IPC Low Density)
3D model CY37064VP44-A44 (44-Pin Thin Plastic Quad Flat Pack 0.8 mm Pitch)
pins: 1 I/O5/TCK (io), 2 I/O6 (io), 3 I/O7 (io), 4 CLK2/IN0 (in), 5 JTAGEN (in), 6 GND (power), 7 CLK0/IN1 (in), 8 I/O8 (io), 9 I/O9 (io), 10 I/O10 (io), 11 I/O11 (io), 12 I/O12 (io), 13 I/O13/TMS (io), 14 I/O14 (io), 15 I/O15 (io), 16 VCC (power), 17 GND (power), 18 I/O16 (io), 19 I/O17 (io), 20 I/O18 (io), 21 I/O19/TDO (io), 22 I/O20 (io), 23 I/O21 (io), 24 I/O22 (io), 25 I/O23 (io), 26 CLK3/IN2 (in), 27 IN3 (in), 28 GND (power), 29 CLK1/IN4 (in), 30 I/O24 (io), 31 I/O25 (io), 32 I/O26 (io), 33 I/O27/TDI (io), 34 I/O28 (io), 35 I/O29 (io), 36 I/O30 (io), 37 I/O31 (io), 38 VCCO (power), 39 GND (power), 40 I/O0 (io), 41 I/O1 (io), 42 I/O2 (io), 43 I/O3 (io), 44 I/O4 (io)

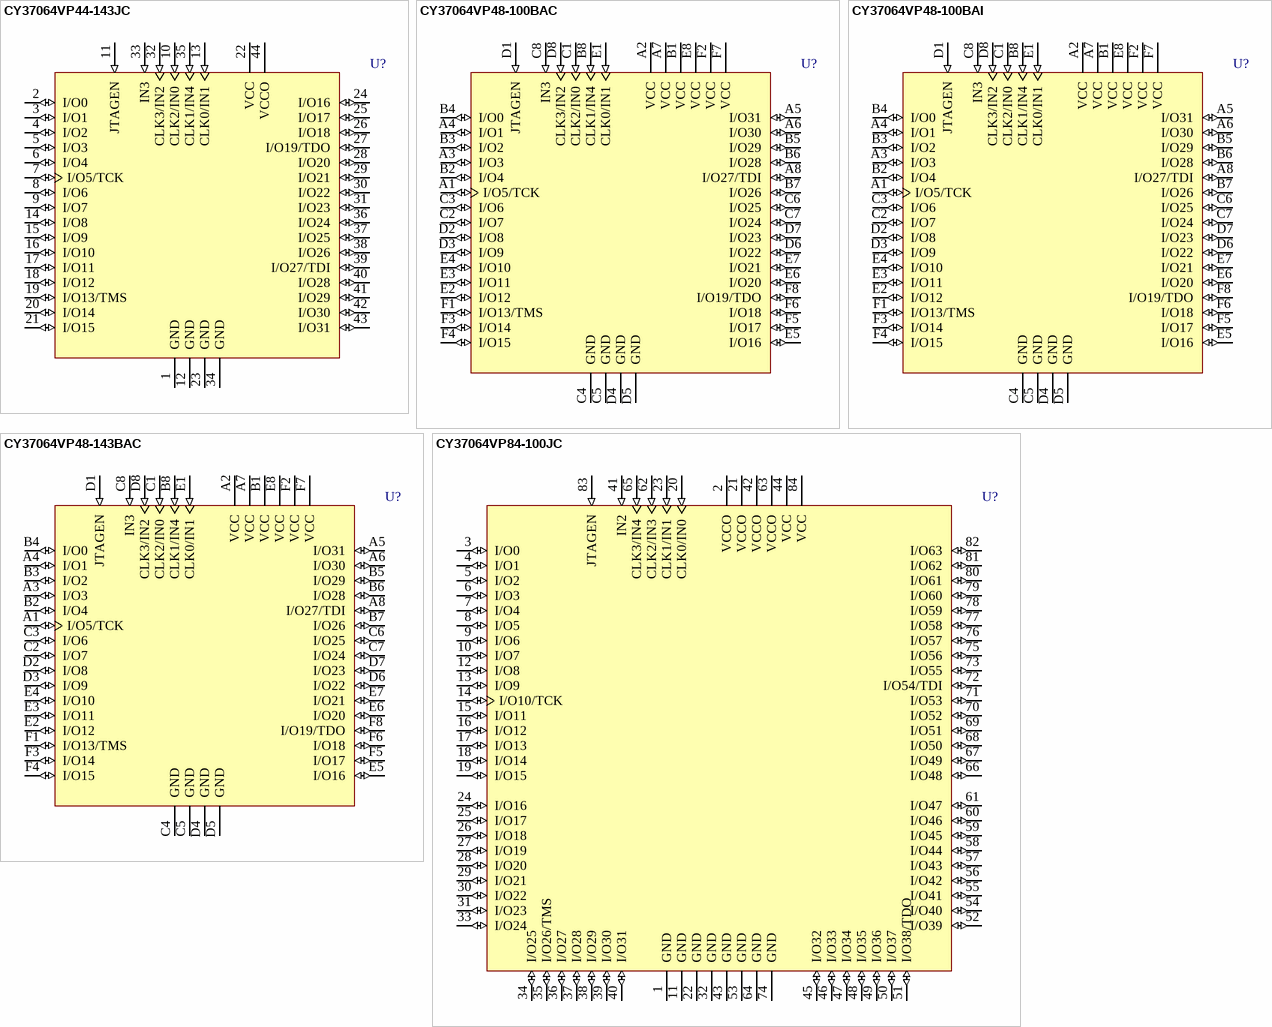
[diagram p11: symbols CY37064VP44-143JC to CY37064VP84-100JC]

## CY37064VP44-143JC
designator U?
Ultra37000 3.3V, ISR High-Performance CPLD; ComponentAvailability: Obsolete
footprint J67_N (Leaded Chip Carrier, 44-Leads, Body 16.6x16.6mm, Pitch 1.27mm, IPC Medium Density)
footprint J67_L (Leaded Chip Carrier, 44-Leads, Body 16.6x16.6mm, Pitch 1.27mm, IPC High Density)
footprint J67_M (Leaded Chip Carrier, 44-Leads, Body 16.6x16.6mm, Pitch 1.27mm, IPC Low Density)
3D model CY37064VP44-J67 (44-Pin Plastic Leaded Chip Carrier 1.27 mm Pitch)
pins: 1 GND (power), 2 I/O0 (io), 3 I/O1 (io), 4 I/O2 (io), 5 I/O3 (io), 6 I/O4 (io), 7 I/O5/TCK (io), 8 I/O6 (io), 9 I/O7 (io), 10 CLK2/IN0 (in), 11 JTAGEN (in), 12 GND (power), 13 CLK0/IN1 (in), 14 I/O8 (io), 15 I/O9 (io), 16 I/O10 (io), 17 I/O11 (io), 18 I/O12 (io), 19 I/O13/TMS (io), 20 I/O14 (io), 21 I/O15 (io), 22 VCC (power), 23 GND (power), 24 I/O16 (io), 25 I/O17 (io), 26 I/O18 (io), 27 I/O19/TDO (io), 28 I/O20 (io), 29 I/O21 (io), 30 I/O22 (io), 31 I/O23 (io), 32 CLK3/IN2 (in), 33 IN3 (in), 34 GND (power), 35 CLK1/IN4 (in), 36 I/O24 (io), 37 I/O25 (io), 38 I/O26 (io), 39 I/O27/TDI (io), 40 I/O28 (io), 41 I/O29 (io), 42 I/O30 (io), 43 I/O31 (io), 44 VCCO (power)

## CY37064VP48-100BAC
designator U?
Ultra37000 3.3V, ISR High-Performance CPLD
footprint BA50 (BGA, 48-Leads, Body 7x7mm, Pitch 0.8mm)
3D model CY37064VP48-BA50 (48-Ball Thin Ball Grid Array 0.8 mm Pitch)
pins: A1 I/O5/TCK (io), A2 VCC (power), A3 I/O3 (io), A4 I/O1 (io), A5 I/O31 (io), A6 I/O30 (io), A7 VCC (power), A8 I/O27/TDI (io), B1 VCC (power), B2 I/O4 (io), B3 I/O2 (io), B4 I/O0 (io), B5 I/O29 (io), B6 I/O28 (io), B7 I/O26 (io), B8 CLK1/IN4 (in), C1 CLK2/IN0 (in), C2 I/O7 (io), C3 I/O6 (io), C4 GND (power), C5 GND (power), C6 I/O25 (io), C7 I/O24 (io), C8 IN3 (in), D1 JTAGEN (in), D2 I/O8 (io), D3 I/O9 (io), D4 GND (power), D5 GND (power), D6 I/O22 (io), D7 I/O23 (io), D8 CLK3/IN2 (in), E1 CLK0/IN1 (in), E2 I/O12 (io), E3 I/O11 (io), E4 I/O10 (io), E5 I/O16 (io), E6 I/O20 (io), E7 I/O21 (io), E8 VCC (power), F1 I/O13/TMS (io), F2 VCC (power), F3 I/O14 (io), F4 I/O15 (io), F5 I/O17 (io), F6 I/O18 (io), F7 VCC (power), F8 I/O19/TDO (io)

## CY37064VP48-100BAI
designator U?
Ultra37000 3.3V, ISR High-Performance CPLD
footprint BA50 (BGA, 48-Leads, Body 7x7mm, Pitch 0.8mm)
3D model CY37064VP48-BA50 (48-Ball Thin Ball Grid Array 0.8 mm Pitch)
pins: A1 I/O5/TCK (io), A2 VCC (power), A3 I/O3 (io), A4 I/O1 (io), A5 I/O31 (io), A6 I/O30 (io), A7 VCC (power), A8 I/O27/TDI (io), B1 VCC (power), B2 I/O4 (io), B3 I/O2 (io), B4 I/O0 (io), B5 I/O29 (io), B6 I/O28 (io), B7 I/O26 (io), B8 CLK1/IN4 (in), C1 CLK2/IN0 (in), C2 I/O7 (io), C3 I/O6 (io), C4 GND (power), C5 GND (power), C6 I/O25 (io), C7 I/O24 (io), C8 IN3 (in), D1 JTAGEN (in), D2 I/O8 (io), D3 I/O9 (io), D4 GND (power), D5 GND (power), D6 I/O22 (io), D7 I/O23 (io), D8 CLK3/IN2 (in), E1 CLK0/IN1 (in), E2 I/O12 (io), E3 I/O11 (io), E4 I/O10 (io), E5 I/O16 (io), E6 I/O20 (io), E7 I/O21 (io), E8 VCC (power), F1 I/O13/TMS (io), F2 VCC (power), F3 I/O14 (io), F4 I/O15 (io), F5 I/O17 (io), F6 I/O18 (io), F7 VCC (power), F8 I/O19/TDO (io)

## CY37064VP48-143BAC
designator U?
Ultra37000 3.3V, ISR High-Performance CPLD
footprint BA50 (BGA, 48-Leads, Body 7x7mm, Pitch 0.8mm)
3D model CY37064VP48-BA50 (48-Ball Thin Ball Grid Array 0.8 mm Pitch)
pins: A1 I/O5/TCK (io), A2 VCC (power), A3 I/O3 (io), A4 I/O1 (io), A5 I/O31 (io), A6 I/O30 (io), A7 VCC (power), A8 I/O27/TDI (io), B1 VCC (power), B2 I/O4 (io), B3 I/O2 (io), B4 I/O0 (io), B5 I/O29 (io), B6 I/O28 (io), B7 I/O26 (io), B8 CLK1/IN4 (in), C1 CLK2/IN0 (in), C2 I/O7 (io), C3 I/O6 (io), C4 GND (power), C5 GND (power), C6 I/O25 (io), C7 I/O24 (io), C8 IN3 (in), D1 JTAGEN (in), D2 I/O8 (io), D3 I/O9 (io), D4 GND (power), D5 GND (power), D6 I/O22 (io), D7 I/O23 (io), D8 CLK3/IN2 (in), E1 CLK0/IN1 (in), E2 I/O12 (io), E3 I/O11 (io), E4 I/O10 (io), E5 I/O16 (io), E6 I/O20 (io), E7 I/O21 (io), E8 VCC (power), F1 I/O13/TMS (io), F2 VCC (power), F3 I/O14 (io), F4 I/O15 (io), F5 I/O17 (io), F6 I/O18 (io), F7 VCC (power), F8 I/O19/TDO (io)

## CY37064VP84-100JC
designator U?
Ultra37000 3.3V, ISR High-Performance CPLD; ComponentAvailability: Obsolete
footprint J83_N (Leaded Chip Carrier, 84-Leads, Body 29.3x29.3mm, Pitch 1.27mm, IPC Medium Density)
footprint J83_L (Leaded Chip Carrier, 84-Leads, Body 29.3x29.3mm, Pitch 1.27mm, IPC High Density)
footprint J83_M (Leaded Chip Carrier, 84-Leads, Body 29.3x29.3mm, Pitch 1.27mm, IPC Low Density)
3D model CY37064VP84-J83 (84-Pin Plastic Leaded Chip Carrier 1.27 mm Pitch)
pins: 1 GND (power), 2 VCCO (power), 3 I/O0 (io), 4 I/O1 (io), 5 I/O2 (io), 6 I/O3 (io), 7 I/O4 (io), 8 I/O5 (io), 9 I/O6 (io), 10 I/O7 (io), 11 GND (power), 12 I/O8 (io), 13 I/O9 (io), 14 I/O10/TCK (io), 15 I/O11 (io), 16 I/O12 (io), 17 I/O13 (io), 18 I/O14 (io), 19 I/O15 (io), 20 CLK0/IN0 (in), 21 VCCO (power), 22 GND (power), 23 CLK1/IN1 (in), 24 I/O16 (io), 25 I/O17 (io), 26 I/O18 (io), 27 I/O19 (io), 28 I/O20 (io), 29 I/O21 (io), 30 I/O22 (io), 31 I/O23 (io), 32 GND (power), 33 I/O24 (io), 34 I/O25 (io), 35 I/O26/TMS (io), 36 I/O27 (io), 37 I/O28 (io), 38 I/O29 (io), 39 I/O30 (io), 40 I/O31 (io), 41 IN2 (in), 42 VCCO (power), 43 GND (power), 44 VCC (power), 45 I/O32 (io), 46 I/O33 (io), 47 I/O34 (io), 48 I/O35 (io), 49 I/O36 (io), 50 I/O37 (io), 51 I/O38/TDO (io), 52 I/O39 (io), 53 GND (power), 54 I/O40 (io), 55 I/O41 (io), 56 I/O42 (io), 57 I/O43 (io), 58 I/O44 (io), 59 I/O45 (io), 60 I/O46 (io), 61 I/O47 (io), 62 CLK2/IN3 (in), 63 VCCO (power), 64 GND (power), 65 CLK3/IN4 (in), 66 I/O48 (io), 67 I/O49 (io), 68 I/O50 (io), 69 I/O51 (io), 70 I/O52 (io), 71 I/O53 (io), 72 I/O54/TDI (io), 73 I/O55 (io), 74 GND (power), 75 I/O56 (io), 76 I/O57 (io), 77 I/O58 (io), 78 I/O59 (io), 79 I/O60 (io), 80 I/O61 (io), 81 I/O62 (io), 82 I/O63 (io), 83 JTAGEN (in), 84 VCC (power)

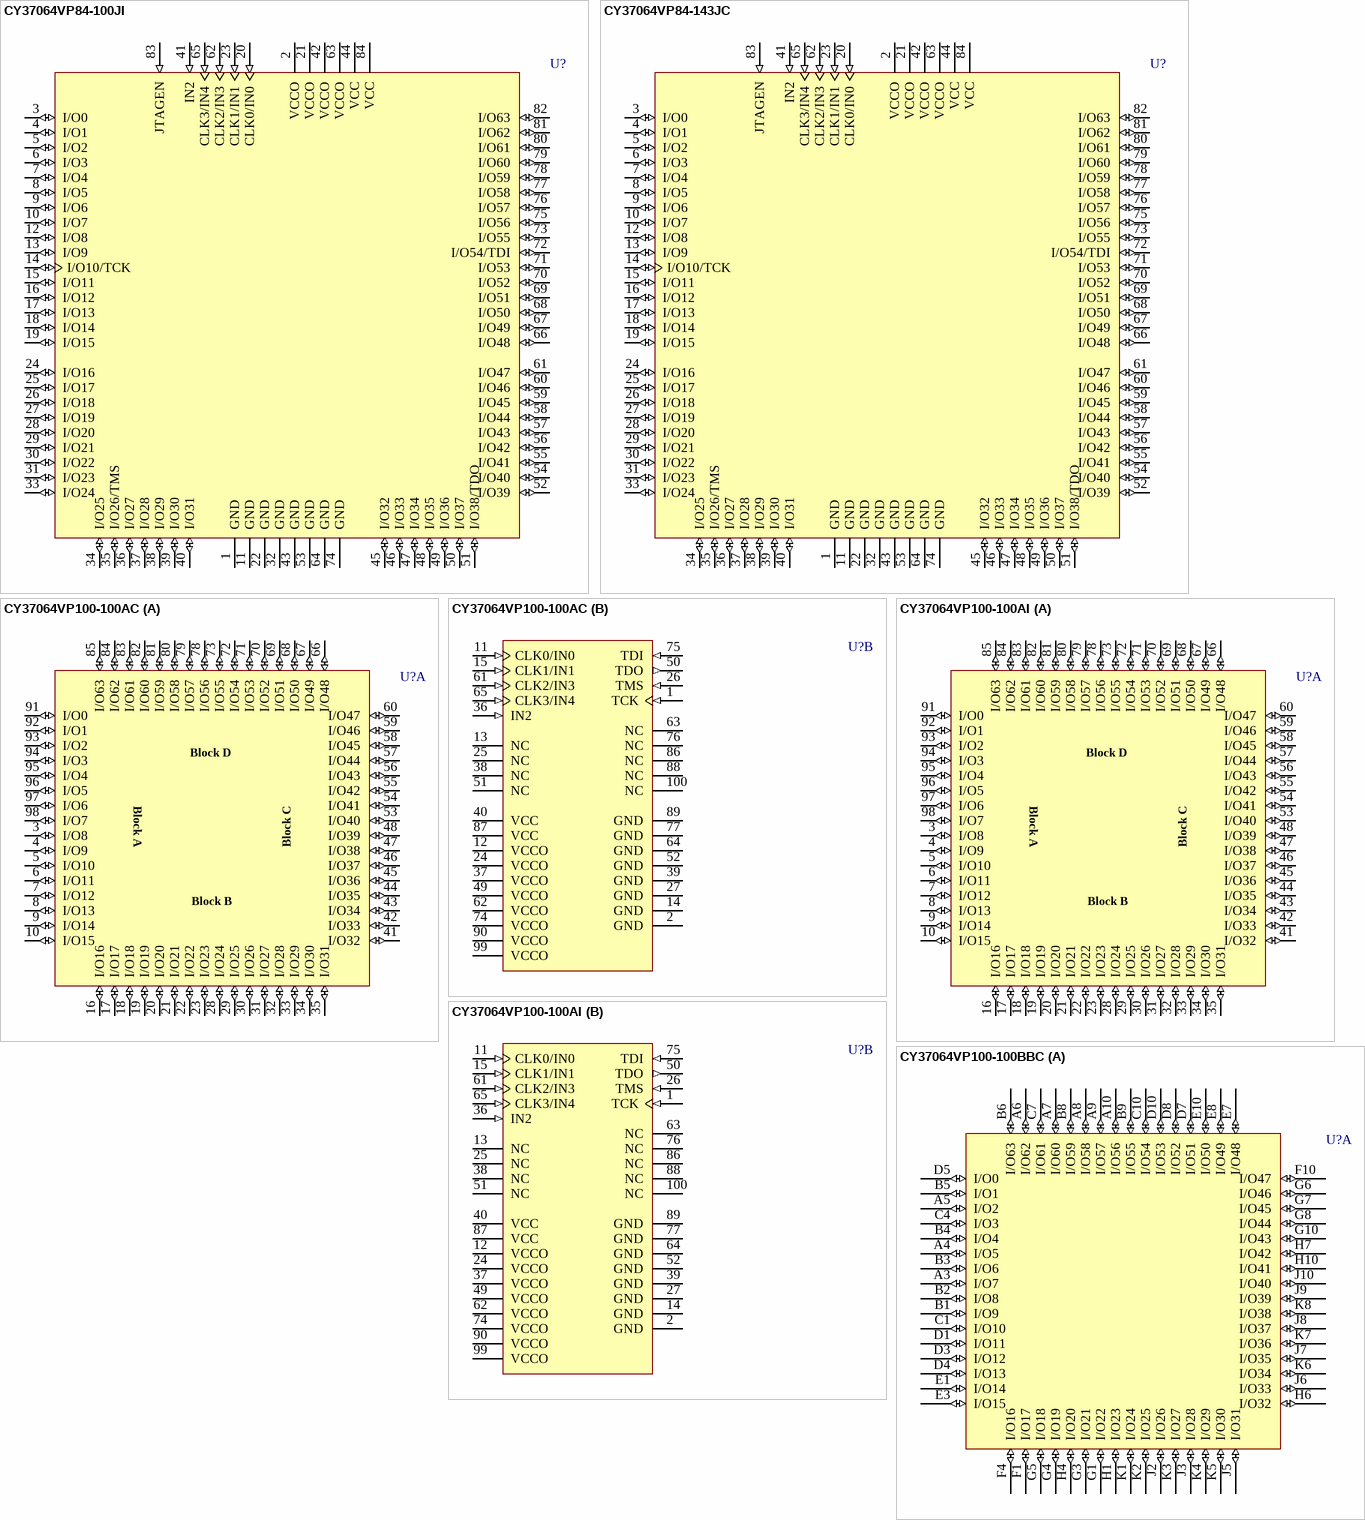
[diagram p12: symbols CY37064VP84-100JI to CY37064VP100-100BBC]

## CY37064VP84-100JI
designator U?
Ultra37000 3.3V, ISR High-Performance CPLD; ComponentAvailability: Obsolete
footprint J83_N (Leaded Chip Carrier, 84-Leads, Body 29.3x29.3mm, Pitch 1.27mm, IPC Medium Density)
footprint J83_L (Leaded Chip Carrier, 84-Leads, Body 29.3x29.3mm, Pitch 1.27mm, IPC High Density)
footprint J83_M (Leaded Chip Carrier, 84-Leads, Body 29.3x29.3mm, Pitch 1.27mm, IPC Low Density)
3D model CY37064VP84-J83 (84-Pin Plastic Leaded Chip Carrier 1.27 mm Pitch)
pins: 1 GND (power), 2 VCCO (power), 3 I/O0 (io), 4 I/O1 (io), 5 I/O2 (io), 6 I/O3 (io), 7 I/O4 (io), 8 I/O5 (io), 9 I/O6 (io), 10 I/O7 (io), 11 GND (power), 12 I/O8 (io), 13 I/O9 (io), 14 I/O10/TCK (io), 15 I/O11 (io), 16 I/O12 (io), 17 I/O13 (io), 18 I/O14 (io), 19 I/O15 (io), 20 CLK0/IN0 (in), 21 VCCO (power), 22 GND (power), 23 CLK1/IN1 (in), 24 I/O16 (io), 25 I/O17 (io), 26 I/O18 (io), 27 I/O19 (io), 28 I/O20 (io), 29 I/O21 (io), 30 I/O22 (io), 31 I/O23 (io), 32 GND (power), 33 I/O24 (io), 34 I/O25 (io), 35 I/O26/TMS (io), 36 I/O27 (io), 37 I/O28 (io), 38 I/O29 (io), 39 I/O30 (io), 40 I/O31 (io), 41 IN2 (in), 42 VCCO (power), 43 GND (power), 44 VCC (power), 45 I/O32 (io), 46 I/O33 (io), 47 I/O34 (io), 48 I/O35 (io), 49 I/O36 (io), 50 I/O37 (io), 51 I/O38/TDO (io), 52 I/O39 (io), 53 GND (power), 54 I/O40 (io), 55 I/O41 (io), 56 I/O42 (io), 57 I/O43 (io), 58 I/O44 (io), 59 I/O45 (io), 60 I/O46 (io), 61 I/O47 (io), 62 CLK2/IN3 (in), 63 VCCO (power), 64 GND (power), 65 CLK3/IN4 (in), 66 I/O48 (io), 67 I/O49 (io), 68 I/O50 (io), 69 I/O51 (io), 70 I/O52 (io), 71 I/O53 (io), 72 I/O54/TDI (io), 73 I/O55 (io), 74 GND (power), 75 I/O56 (io), 76 I/O57 (io), 77 I/O58 (io), 78 I/O59 (io), 79 I/O60 (io), 80 I/O61 (io), 81 I/O62 (io), 82 I/O63 (io), 83 JTAGEN (in), 84 VCC (power)

## CY37064VP84-143JC
designator U?
Ultra37000 3.3V, ISR High-Performance CPLD; ComponentAvailability: Obsolete
footprint J83_N (Leaded Chip Carrier, 84-Leads, Body 29.3x29.3mm, Pitch 1.27mm, IPC Medium Density)
footprint J83_L (Leaded Chip Carrier, 84-Leads, Body 29.3x29.3mm, Pitch 1.27mm, IPC High Density)
footprint J83_M (Leaded Chip Carrier, 84-Leads, Body 29.3x29.3mm, Pitch 1.27mm, IPC Low Density)
3D model CY37064VP84-J83 (84-Pin Plastic Leaded Chip Carrier 1.27 mm Pitch)
pins: 1 GND (power), 2 VCCO (power), 3 I/O0 (io), 4 I/O1 (io), 5 I/O2 (io), 6 I/O3 (io), 7 I/O4 (io), 8 I/O5 (io), 9 I/O6 (io), 10 I/O7 (io), 11 GND (power), 12 I/O8 (io), 13 I/O9 (io), 14 I/O10/TCK (io), 15 I/O11 (io), 16 I/O12 (io), 17 I/O13 (io), 18 I/O14 (io), 19 I/O15 (io), 20 CLK0/IN0 (in), 21 VCCO (power), 22 GND (power), 23 CLK1/IN1 (in), 24 I/O16 (io), 25 I/O17 (io), 26 I/O18 (io), 27 I/O19 (io), 28 I/O20 (io), 29 I/O21 (io), 30 I/O22 (io), 31 I/O23 (io), 32 GND (power), 33 I/O24 (io), 34 I/O25 (io), 35 I/O26/TMS (io), 36 I/O27 (io), 37 I/O28 (io), 38 I/O29 (io), 39 I/O30 (io), 40 I/O31 (io), 41 IN2 (in), 42 VCCO (power), 43 GND (power), 44 VCC (power), 45 I/O32 (io), 46 I/O33 (io), 47 I/O34 (io), 48 I/O35 (io), 49 I/O36 (io), 50 I/O37 (io), 51 I/O38/TDO (io), 52 I/O39 (io), 53 GND (power), 54 I/O40 (io), 55 I/O41 (io), 56 I/O42 (io), 57 I/O43 (io), 58 I/O44 (io), 59 I/O45 (io), 60 I/O46 (io), 61 I/O47 (io), 62 CLK2/IN3 (in), 63 VCCO (power), 64 GND (power), 65 CLK3/IN4 (in), 66 I/O48 (io), 67 I/O49 (io), 68 I/O50 (io), 69 I/O51 (io), 70 I/O52 (io), 71 I/O53 (io), 72 I/O54/TDI (io), 73 I/O55 (io), 74 GND (power), 75 I/O56 (io), 76 I/O57 (io), 77 I/O58 (io), 78 I/O59 (io), 79 I/O60 (io), 80 I/O61 (io), 81 I/O62 (io), 82 I/O63 (io), 83 JTAGEN (in), 84 VCC (power)

## CY37064VP100-100AC
designator U?
Ultra37000 3.3V, ISR High-Performance CPLD
footprint A100_N (Thin QFP, 100-Leads, Body 14x14mm, Pitch 0.5mm, IPC Medium Density)
footprint A100_L (Thin QFP, 100-Leads, Body 14x14mm, Pitch 0.5mm, IPC High Density)
footprint A100_M (Thin QFP, 100-Leads, Body 14x14mm, Pitch 0.5mm, IPC Low Density)
3D model CY37064VP100-A100 (100-Pin Thin Quad Flat Pack 0.5 mm Pitch)
part A pins: 3 I/O8 (io), 4 I/O9 (io), 5 I/O10 (io), 6 I/O11 (io), 7 I/O12 (io), 8 I/O13 (io), 9 I/O14 (io), 10 I/O15 (io), 16 I/O16 (io), 17 I/O17 (io), 18 I/O18 (io), 19 I/O19 (io), 20 I/O20 (io), 21 I/O21 (io), 22 I/O22 (io), 23 I/O23 (io), 28 I/O24 (io), 29 I/O25 (io), 30 I/O26 (io), 31 I/O27 (io), 32 I/O28 (io), 33 I/O29 (io), 34 I/O30 (io), 35 I/O31 (io), 41 I/O32 (io), 42 I/O33 (io), 43 I/O34 (io), 44 I/O35 (io), 45 I/O36 (io), 46 I/O37 (io), 47 I/O38 (io), 48 I/O39 (io), 53 I/O40 (io), 54 I/O41 (io), 55 I/O42 (io), 56 I/O43 (io), 57 I/O44 (io), 58 I/O45 (io), 59 I/O46 (io), 60 I/O47 (io), 66 I/O48 (io), 67 I/O49 (io), 68 I/O50 (io), 69 I/O51 (io), 70 I/O52 (io), 71 I/O53 (io), 72 I/O54 (io), 73 I/O55 (io), 78 I/O56 (io), 79 I/O57 (io), 80 I/O58 (io), 81 I/O59 (io), 82 I/O60 (io), 83 I/O61 (io), 84 I/O62 (io), 85 I/O63 (io), 91 I/O0 (io), 92 I/O1 (io), 93 I/O2 (io), 94 I/O3 (io), 95 I/O4 (io), 96 I/O5 (io), 97 I/O6 (io), 98 I/O7 (io)
part B pins: 1 TCK (in), 2 GND (power), 11 CLK0/IN0 (in), 12 VCCO (power), 13 NC, 14 GND (power), 15 CLK1/IN1 (in), 24 VCCO (power), 25 NC, 26 TMS (in), 27 GND (power), 36 IN2 (in), 37 VCCO (power), 38 NC, 39 GND (power), 40 VCC (power), 49 VCCO (power), 50 TDO (out), 51 NC, 52 GND (power), 61 CLK2/IN3 (in), 62 VCCO (power), 63 NC, 64 GND (power), 65 CLK3/IN4 (in), 74 VCCO (power), 75 TDI (in), 76 NC, 77 GND (power), 86 NC, 87 VCC (power), 88 NC, 89 GND (power), 90 VCCO (power), 99 VCCO (power), 100 NC

## CY37064VP100-100AI
designator U?
Ultra37000 3.3V, ISR High-Performance CPLD
footprint A100_N (Thin QFP, 100-Leads, Body 14x14mm, Pitch 0.5mm, IPC Medium Density)
footprint A100_L (Thin QFP, 100-Leads, Body 14x14mm, Pitch 0.5mm, IPC High Density)
footprint A100_M (Thin QFP, 100-Leads, Body 14x14mm, Pitch 0.5mm, IPC Low Density)
3D model CY37064VP100-A100 (100-Pin Thin Quad Flat Pack 0.5 mm Pitch)
part A pins: 3 I/O8 (io), 4 I/O9 (io), 5 I/O10 (io), 6 I/O11 (io), 7 I/O12 (io), 8 I/O13 (io), 9 I/O14 (io), 10 I/O15 (io), 16 I/O16 (io), 17 I/O17 (io), 18 I/O18 (io), 19 I/O19 (io), 20 I/O20 (io), 21 I/O21 (io), 22 I/O22 (io), 23 I/O23 (io), 28 I/O24 (io), 29 I/O25 (io), 30 I/O26 (io), 31 I/O27 (io), 32 I/O28 (io), 33 I/O29 (io), 34 I/O30 (io), 35 I/O31 (io), 41 I/O32 (io), 42 I/O33 (io), 43 I/O34 (io), 44 I/O35 (io), 45 I/O36 (io), 46 I/O37 (io), 47 I/O38 (io), 48 I/O39 (io), 53 I/O40 (io), 54 I/O41 (io), 55 I/O42 (io), 56 I/O43 (io), 57 I/O44 (io), 58 I/O45 (io), 59 I/O46 (io), 60 I/O47 (io), 66 I/O48 (io), 67 I/O49 (io), 68 I/O50 (io), 69 I/O51 (io), 70 I/O52 (io), 71 I/O53 (io), 72 I/O54 (io), 73 I/O55 (io), 78 I/O56 (io), 79 I/O57 (io), 80 I/O58 (io), 81 I/O59 (io), 82 I/O60 (io), 83 I/O61 (io), 84 I/O62 (io), 85 I/O63 (io), 91 I/O0 (io), 92 I/O1 (io), 93 I/O2 (io), 94 I/O3 (io), 95 I/O4 (io), 96 I/O5 (io), 97 I/O6 (io), 98 I/O7 (io)
part B pins: 1 TCK (in), 2 GND (power), 11 CLK0/IN0 (in), 12 VCCO (power), 13 NC, 14 GND (power), 15 CLK1/IN1 (in), 24 VCCO (power), 25 NC, 26 TMS (in), 27 GND (power), 36 IN2 (in), 37 VCCO (power), 38 NC, 39 GND (power), 40 VCC (power), 49 VCCO (power), 50 TDO (out), 51 NC, 52 GND (power), 61 CLK2/IN3 (in), 62 VCCO (power), 63 NC, 64 GND (power), 65 CLK3/IN4 (in), 74 VCCO (power), 75 TDI (in), 76 NC, 77 GND (power), 86 NC, 87 VCC (power), 88 NC, 89 GND (power), 90 VCCO (power), 99 VCCO (power), 100 NC

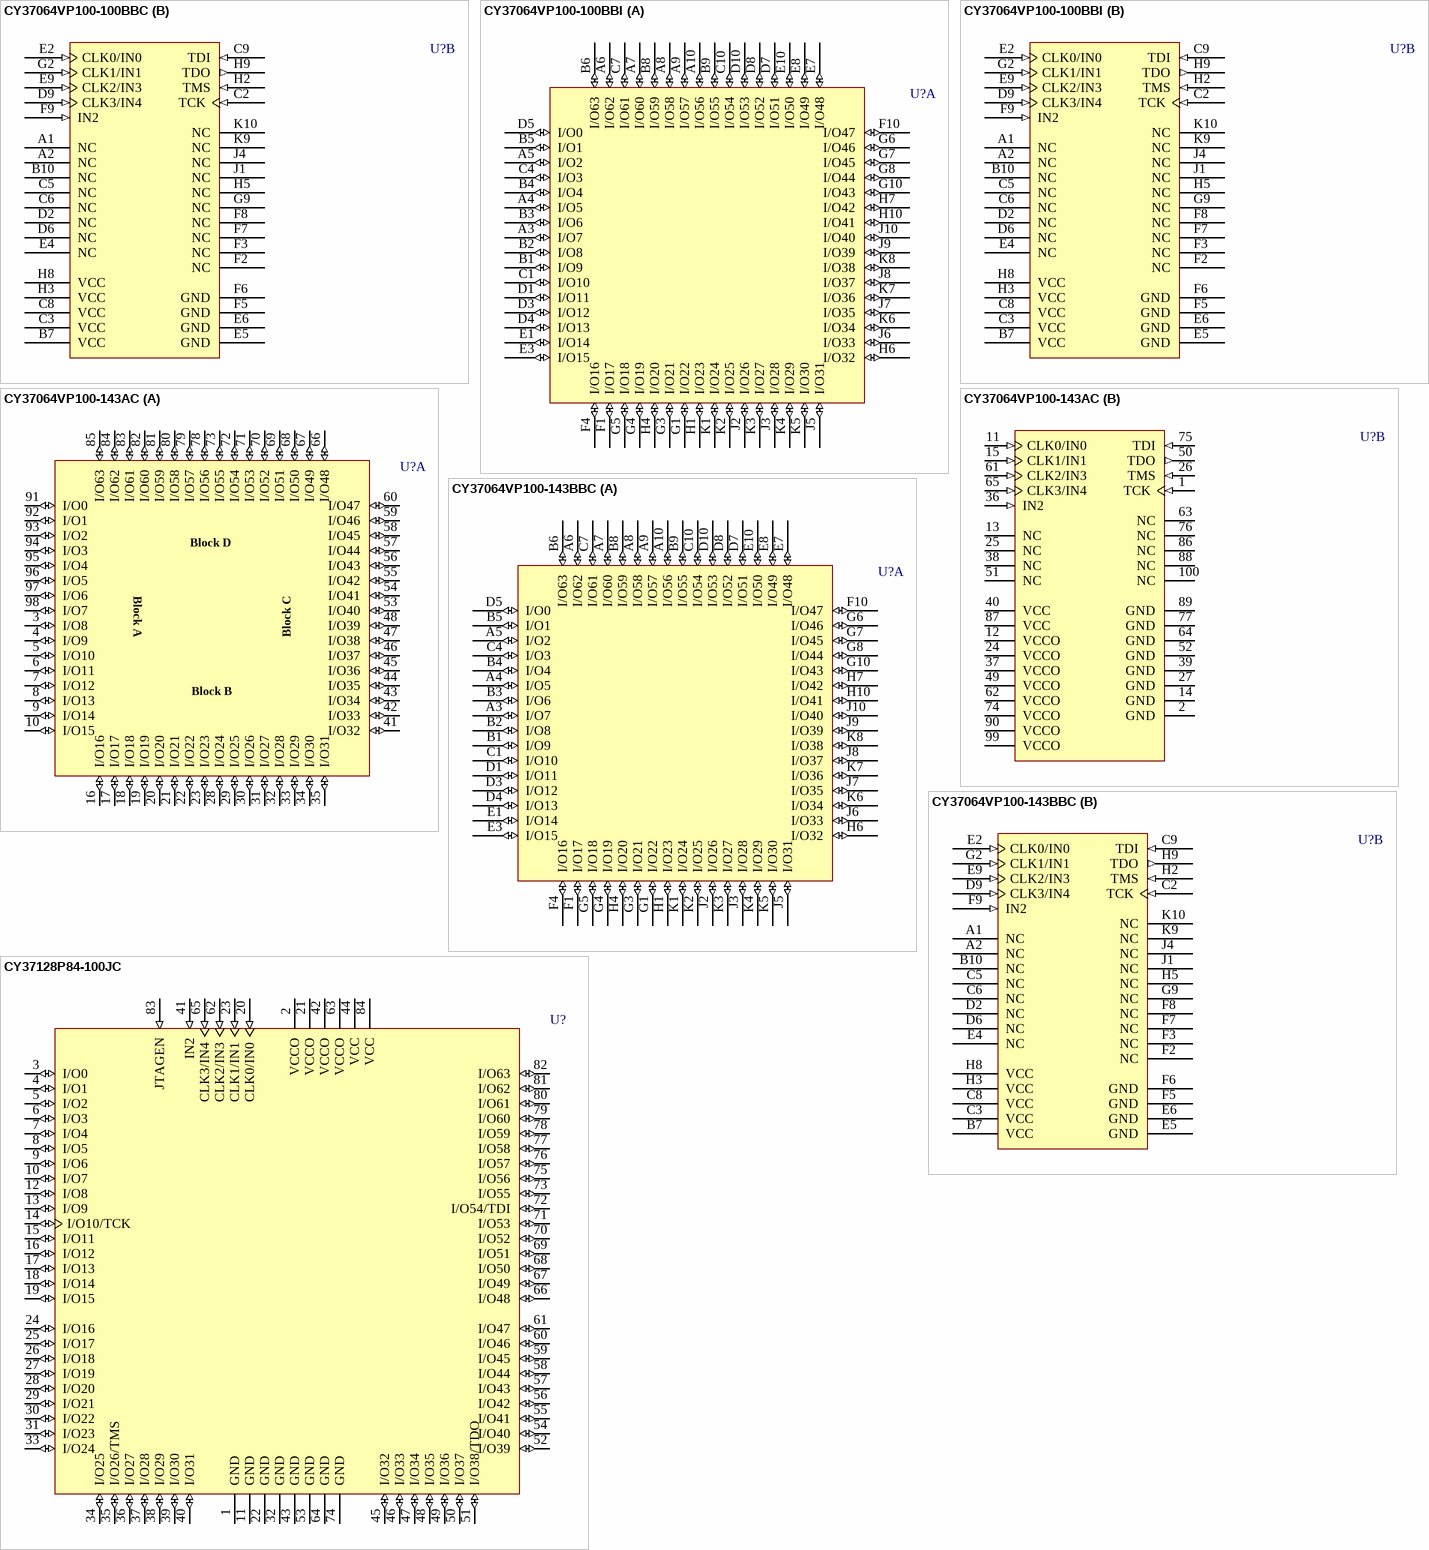
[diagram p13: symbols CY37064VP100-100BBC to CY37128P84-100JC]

## CY37064VP100-100BBC
designator U?
Ultra37000 3.3V, ISR High-Performance CPLD
footprint BB100 (BGA, 100-Leads, Body 11x11mm, Pitch 1mm)
3D model CY37064VP100-BB100 (100-Ball Thin Ball Grid Array 1 mm Pitch)
part A pins: A3 I/O7 (io), A4 I/O5 (io), A5 I/O2 (io), A6 I/O62 (io), A7 I/O60 (io), A8 I/O58 (io), A9 I/O57 (io), A10 I/O56 (io), B1 I/O9 (io), B2 I/O8 (io), B3 I/O6 (io), B4 I/O4 (io), B5 I/O1 (io), B6 I/O63 (io), B8 I/O59 (io), B9 I/O55 (io), C1 I/O10 (io), C4 I/O3 (io), C7 I/O61 (io), C10 I/O54 (io), D1 I/O11 (io), D3 I/O12 (io), D4 I/O13 (io), D5 I/O0 (io), D7 I/O51 (io), D8 I/O52 (io), D10 I/O53 (io), E1 I/O14 (io), E3 I/O15 (io), E7 I/O48 (io), E8 I/O49 (io), E10 I/O50 (io), F1 I/O17 (io), F4 I/O16 (io), F10 I/O47 (io), G1 I/O22 (io), G3 I/O21 (io), G4 I/O19 (io), G5 I/O18 (io), G6 I/O46 (io), G7 I/O45 (io), G8 I/O44 (io), G10 I/O43 (io), H1 I/O23 (io), H4 I/O20 (io), H6 I/O32 (io), H7 I/O42 (io), H10 I/O41 (io), J2 I/O26 (io), J3 I/O28 (io), J5 I/O31 (io), J6 I/O33 (io), J7 I/O35 (io), J8 I/O37 (io), J9 I/O39 (io), J10 I/O40 (io), K1 I/O24 (io), K2 I/O25 (io), K3 I/O27 (io), K4 I/O29 (io), K5 I/O30 (io), K6 I/O34 (io), K7 I/O36 (io), K8 I/O38 (io)
part B pins: A1 NC, A2 NC, B7 VCC (power), B10 NC, C2 TCK (in), C3 VCC (power), C5 NC, C6 NC, C8 VCC (power), C9 TDI (in), D2 NC, D6 NC, D9 CLK3/IN4 (in), E2 CLK0/IN0 (in), E4 NC, E5 GND (power), E6 GND (power), E9 CLK2/IN3 (in), F2 NC, F3 NC, F5 GND (power), F6 GND (power), F7 NC, F8 NC, F9 IN2 (in), G2 CLK1/IN1 (in), G9 NC, H2 TMS (in), H3 VCC (power), H5 NC, H8 VCC (power), H9 TDO (out), J1 NC, J4 NC, K9 NC, K10 NC

## CY37064VP100-100BBI
designator U?
Ultra37000 3.3V, ISR High-Performance CPLD
footprint BB100 (BGA, 100-Leads, Body 11x11mm, Pitch 1mm)
3D model CY37064VP100-BB100 (100-Ball Thin Ball Grid Array 1 mm Pitch)
part A pins: A3 I/O7 (io), A4 I/O5 (io), A5 I/O2 (io), A6 I/O62 (io), A7 I/O60 (io), A8 I/O58 (io), A9 I/O57 (io), A10 I/O56 (io), B1 I/O9 (io), B2 I/O8 (io), B3 I/O6 (io), B4 I/O4 (io), B5 I/O1 (io), B6 I/O63 (io), B8 I/O59 (io), B9 I/O55 (io), C1 I/O10 (io), C4 I/O3 (io), C7 I/O61 (io), C10 I/O54 (io), D1 I/O11 (io), D3 I/O12 (io), D4 I/O13 (io), D5 I/O0 (io), D7 I/O51 (io), D8 I/O52 (io), D10 I/O53 (io), E1 I/O14 (io), E3 I/O15 (io), E7 I/O48 (io), E8 I/O49 (io), E10 I/O50 (io), F1 I/O17 (io), F4 I/O16 (io), F10 I/O47 (io), G1 I/O22 (io), G3 I/O21 (io), G4 I/O19 (io), G5 I/O18 (io), G6 I/O46 (io), G7 I/O45 (io), G8 I/O44 (io), G10 I/O43 (io), H1 I/O23 (io), H4 I/O20 (io), H6 I/O32 (io), H7 I/O42 (io), H10 I/O41 (io), J2 I/O26 (io), J3 I/O28 (io), J5 I/O31 (io), J6 I/O33 (io), J7 I/O35 (io), J8 I/O37 (io), J9 I/O39 (io), J10 I/O40 (io), K1 I/O24 (io), K2 I/O25 (io), K3 I/O27 (io), K4 I/O29 (io), K5 I/O30 (io), K6 I/O34 (io), K7 I/O36 (io), K8 I/O38 (io)
part B pins: A1 NC, A2 NC, B7 VCC (power), B10 NC, C2 TCK (in), C3 VCC (power), C5 NC, C6 NC, C8 VCC (power), C9 TDI (in), D2 NC, D6 NC, D9 CLK3/IN4 (in), E2 CLK0/IN0 (in), E4 NC, E5 GND (power), E6 GND (power), E9 CLK2/IN3 (in), F2 NC, F3 NC, F5 GND (power), F6 GND (power), F7 NC, F8 NC, F9 IN2 (in), G2 CLK1/IN1 (in), G9 NC, H2 TMS (in), H3 VCC (power), H5 NC, H8 VCC (power), H9 TDO (out), J1 NC, J4 NC, K9 NC, K10 NC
